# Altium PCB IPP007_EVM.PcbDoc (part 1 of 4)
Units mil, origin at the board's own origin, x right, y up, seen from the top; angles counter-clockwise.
Board outline 3500.95 x 3103 mil, 6 copper layers (Top Layer, Int1 (GND), Int2 (Sign), Int3 (Sign), Int4 (GND), Bottom Layer), stack 61.068 mil thick; 257 components, 132 nets, 1052 pads, 535 vias.
Unrouted connection lines stored in the file: 3.
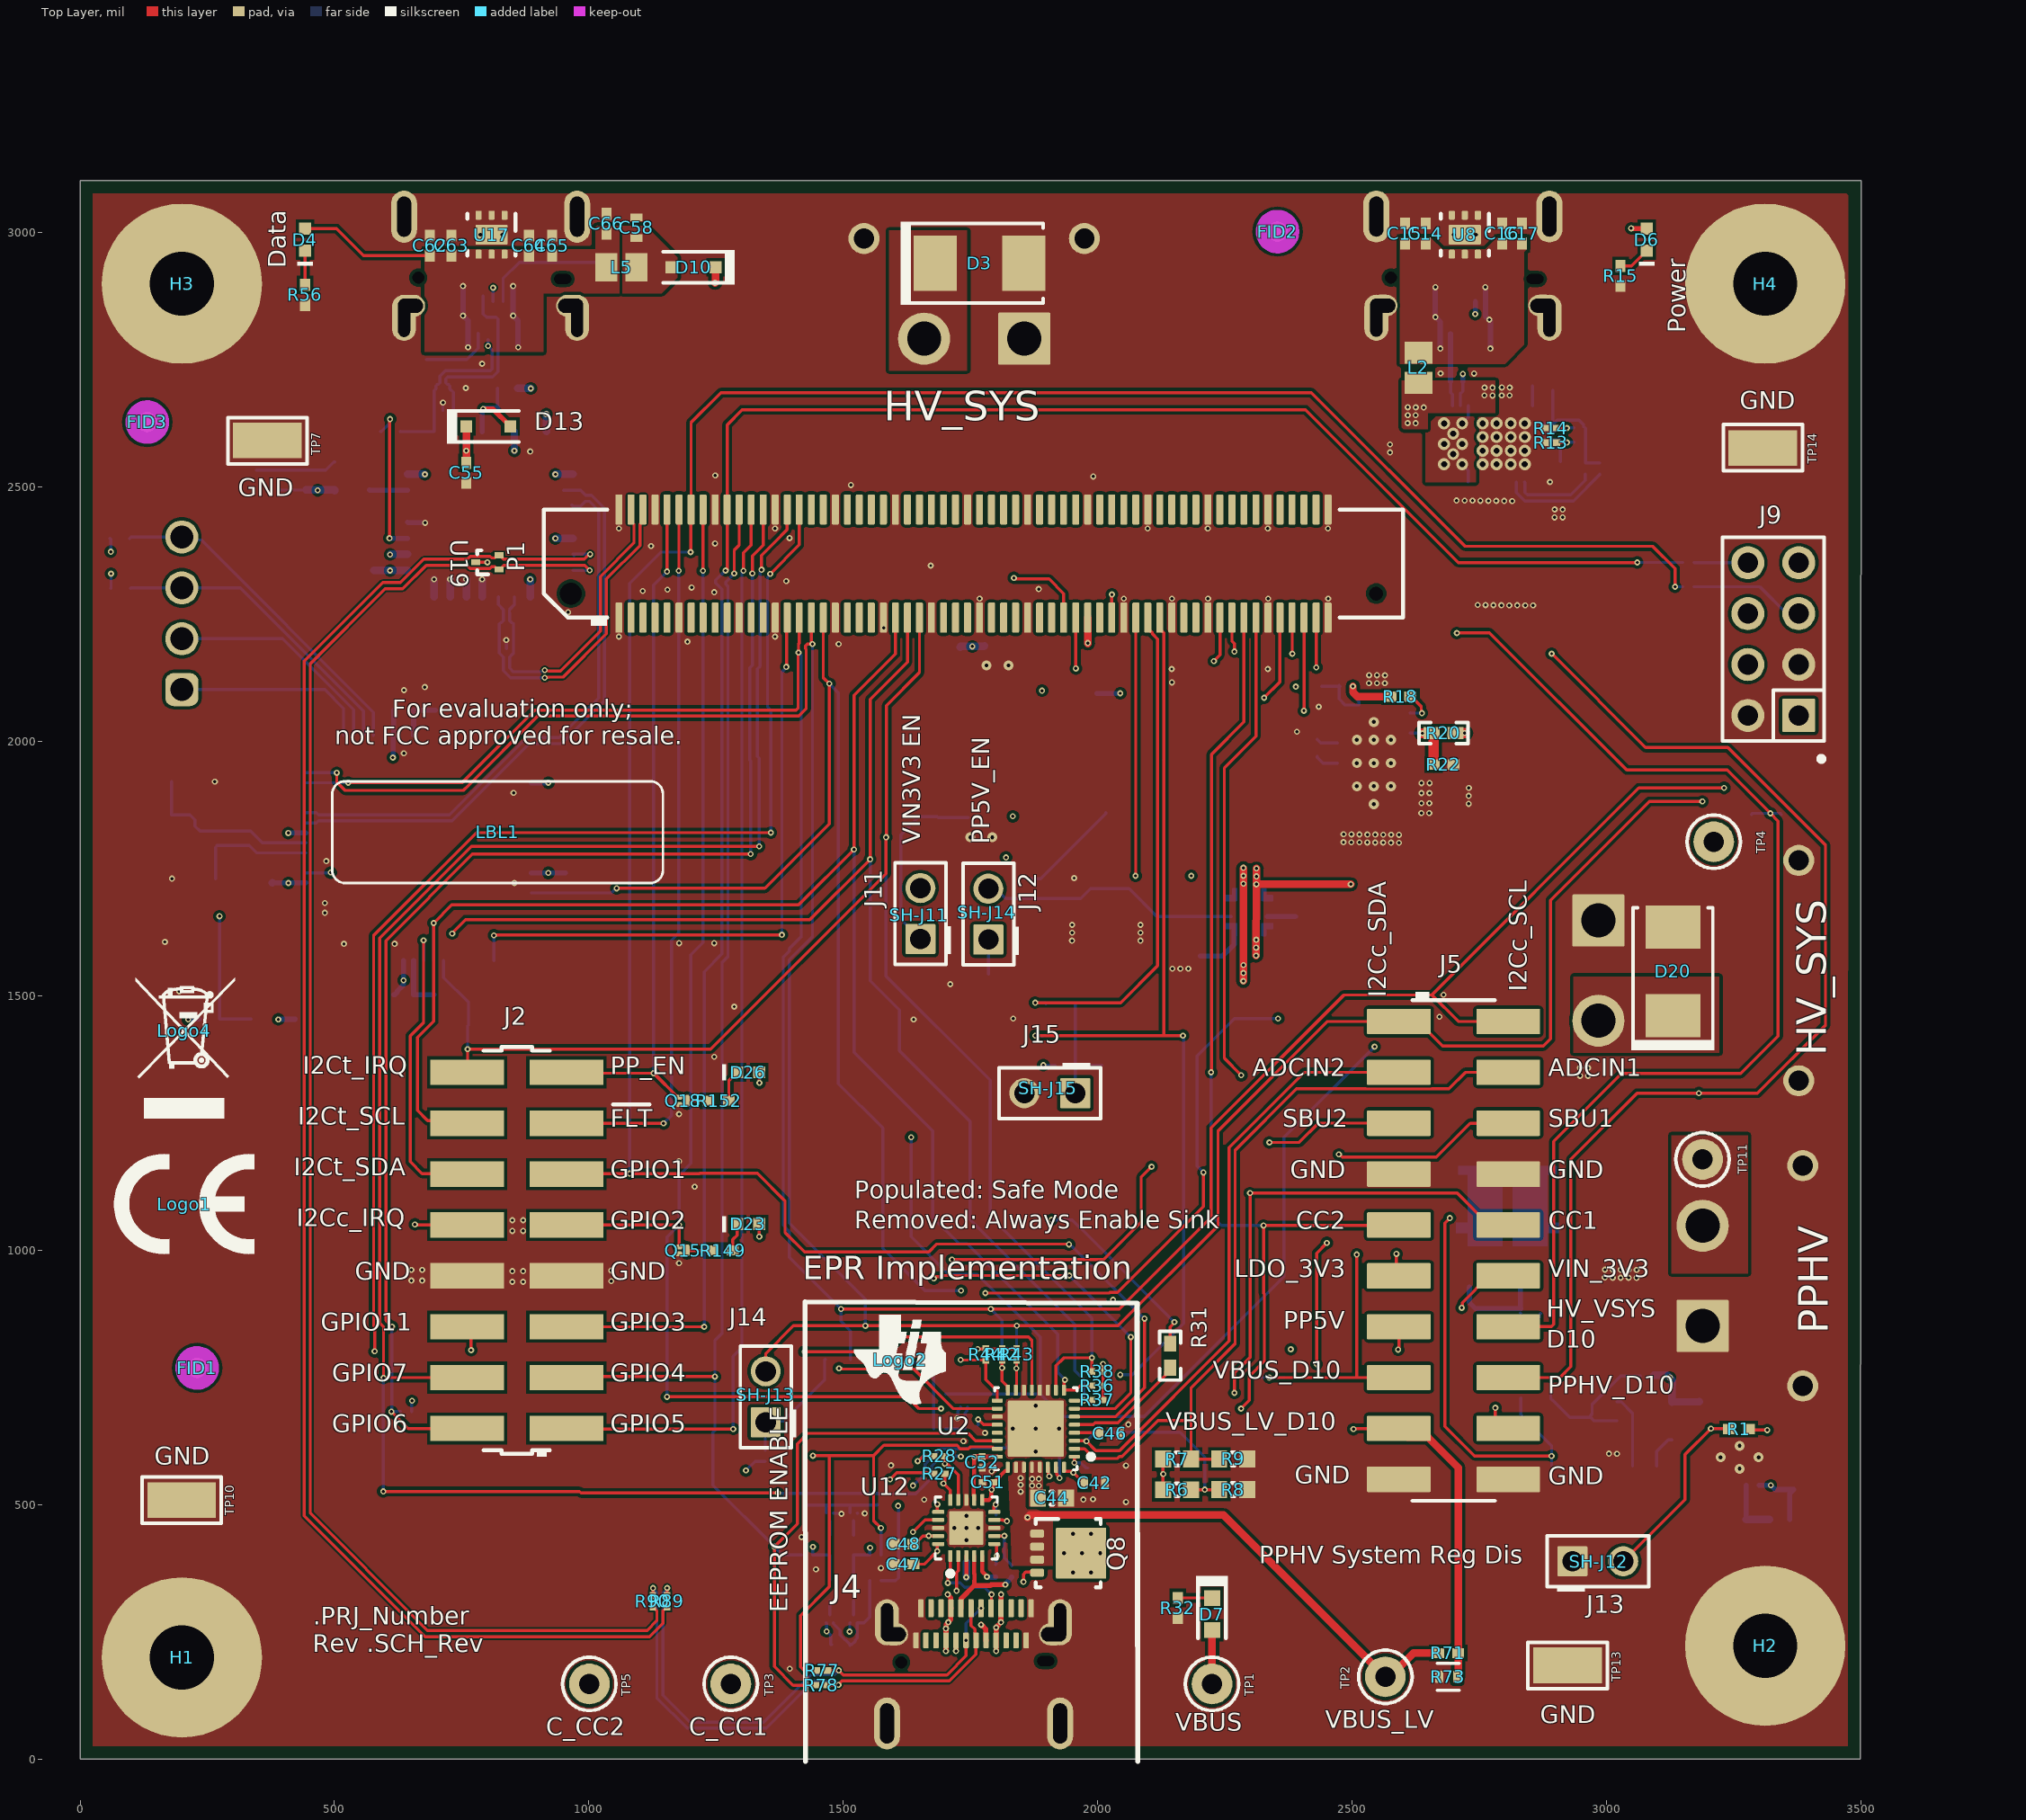
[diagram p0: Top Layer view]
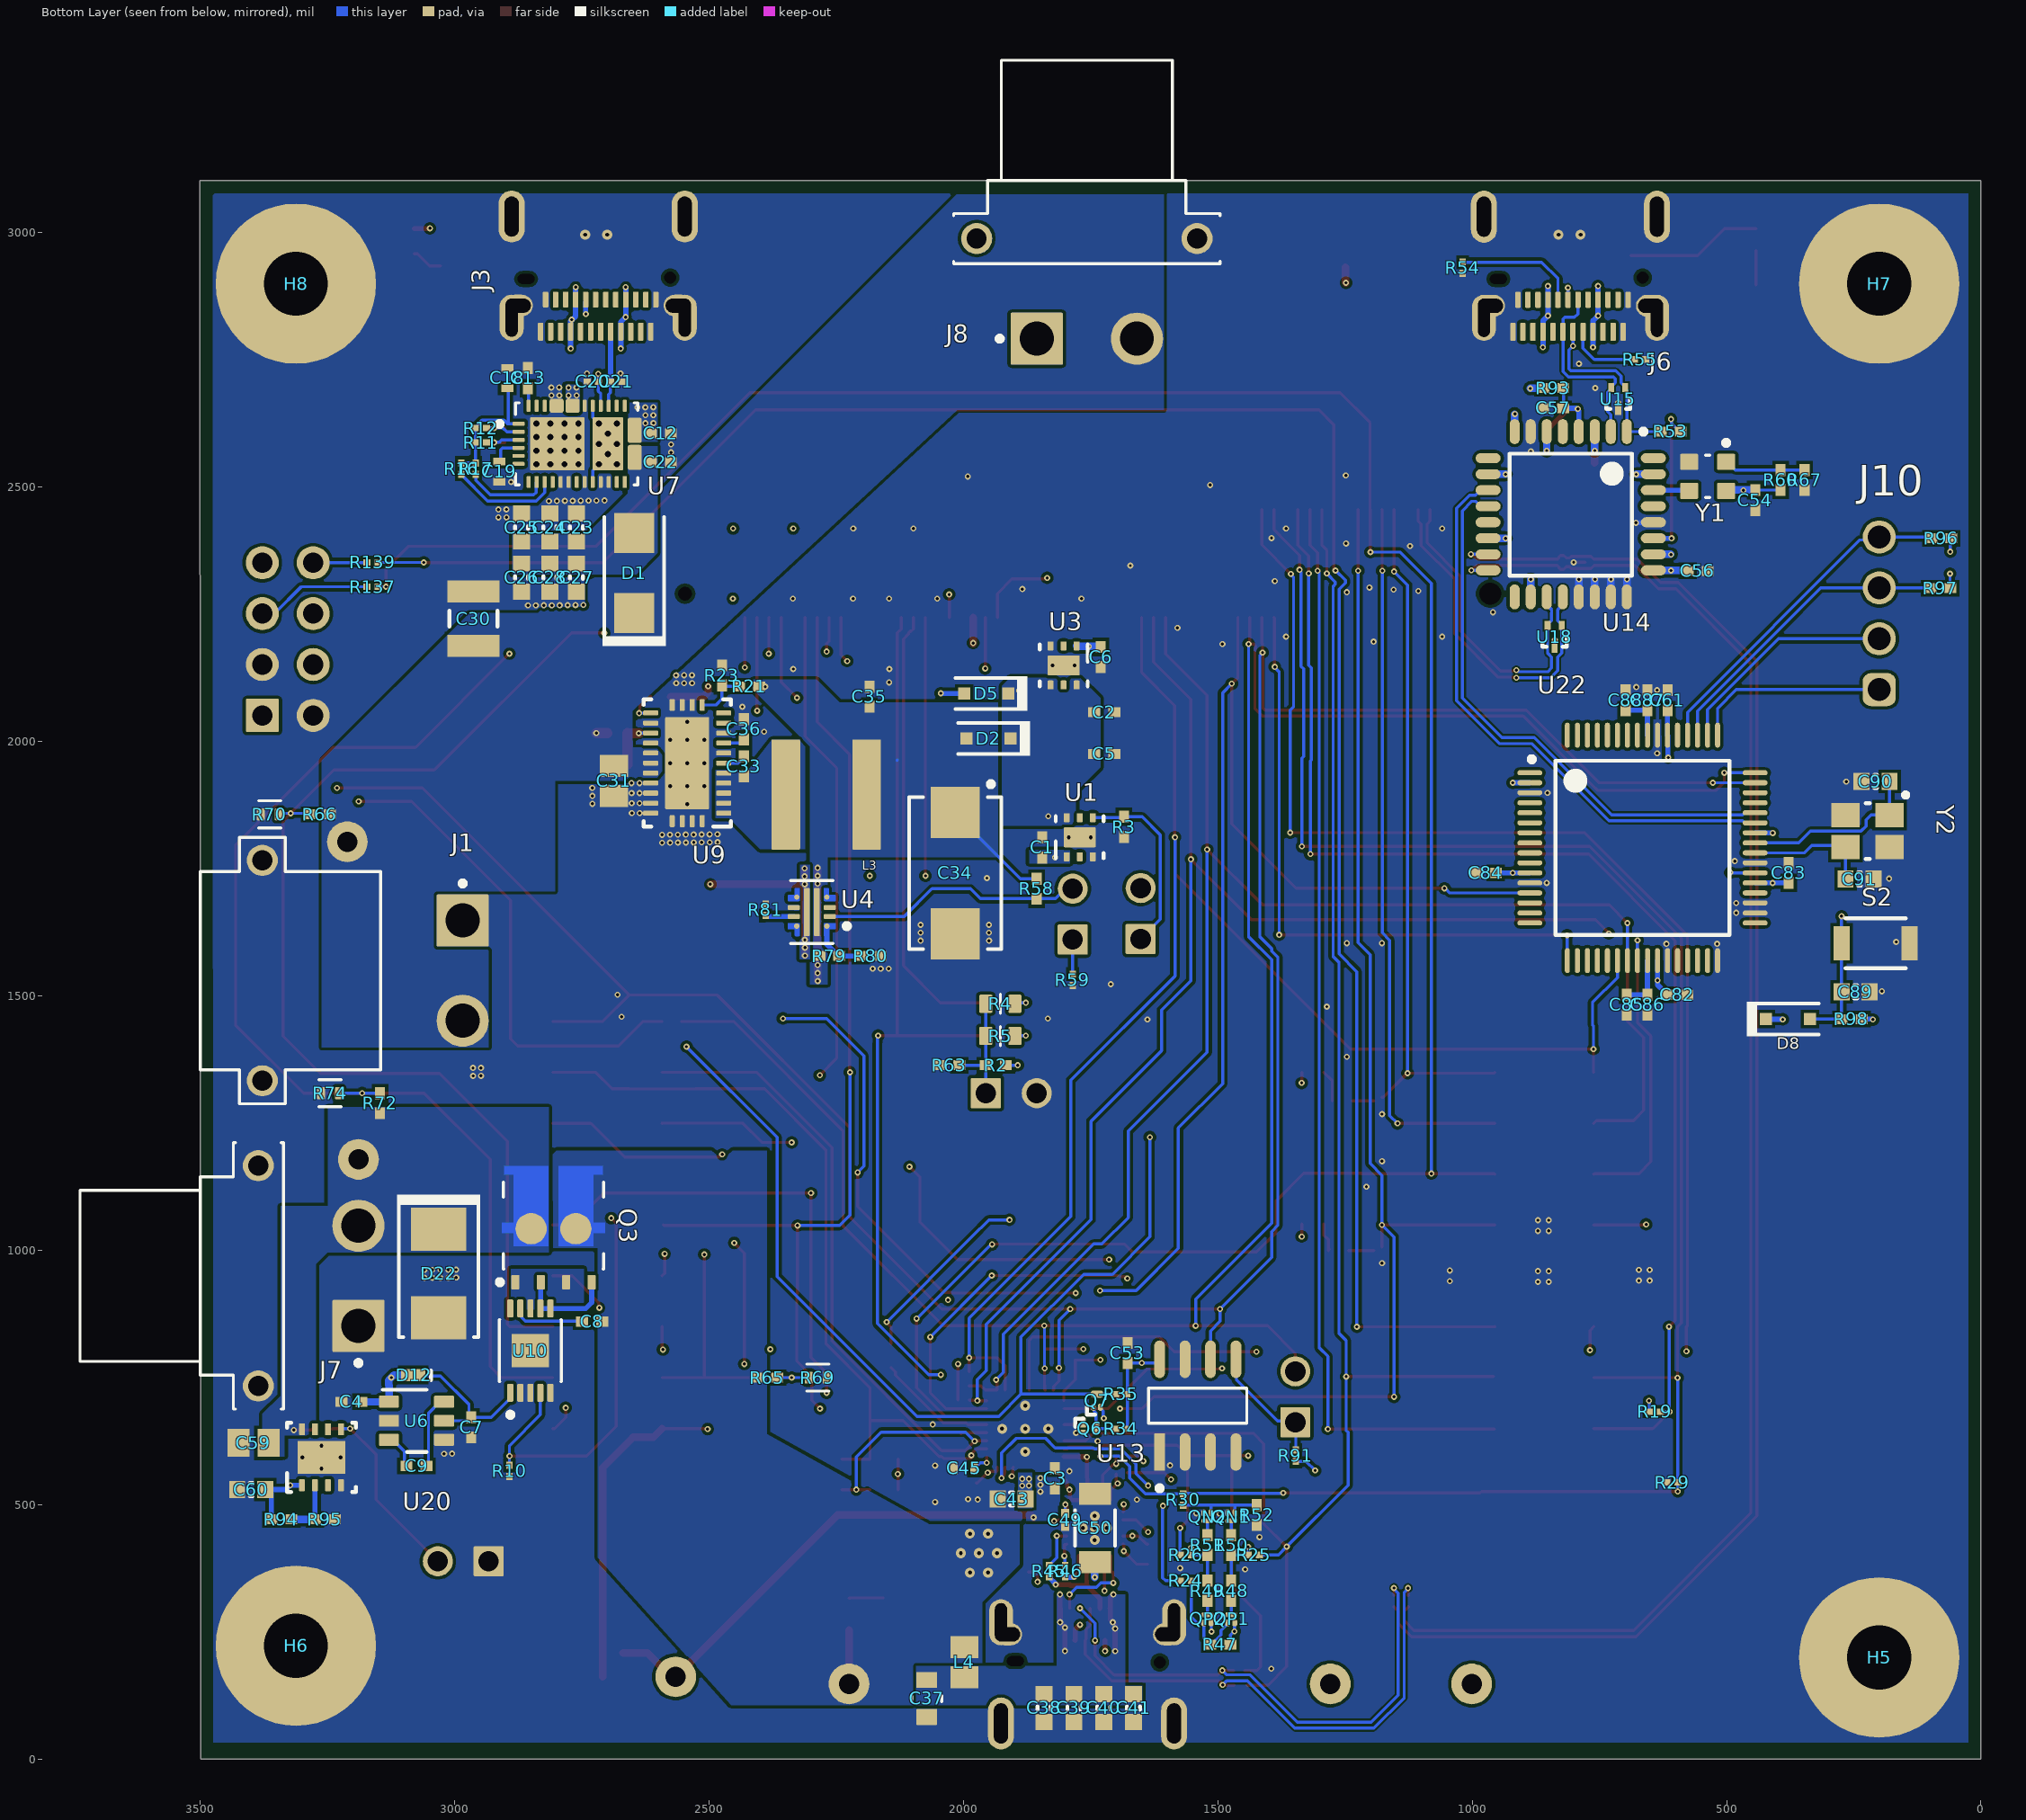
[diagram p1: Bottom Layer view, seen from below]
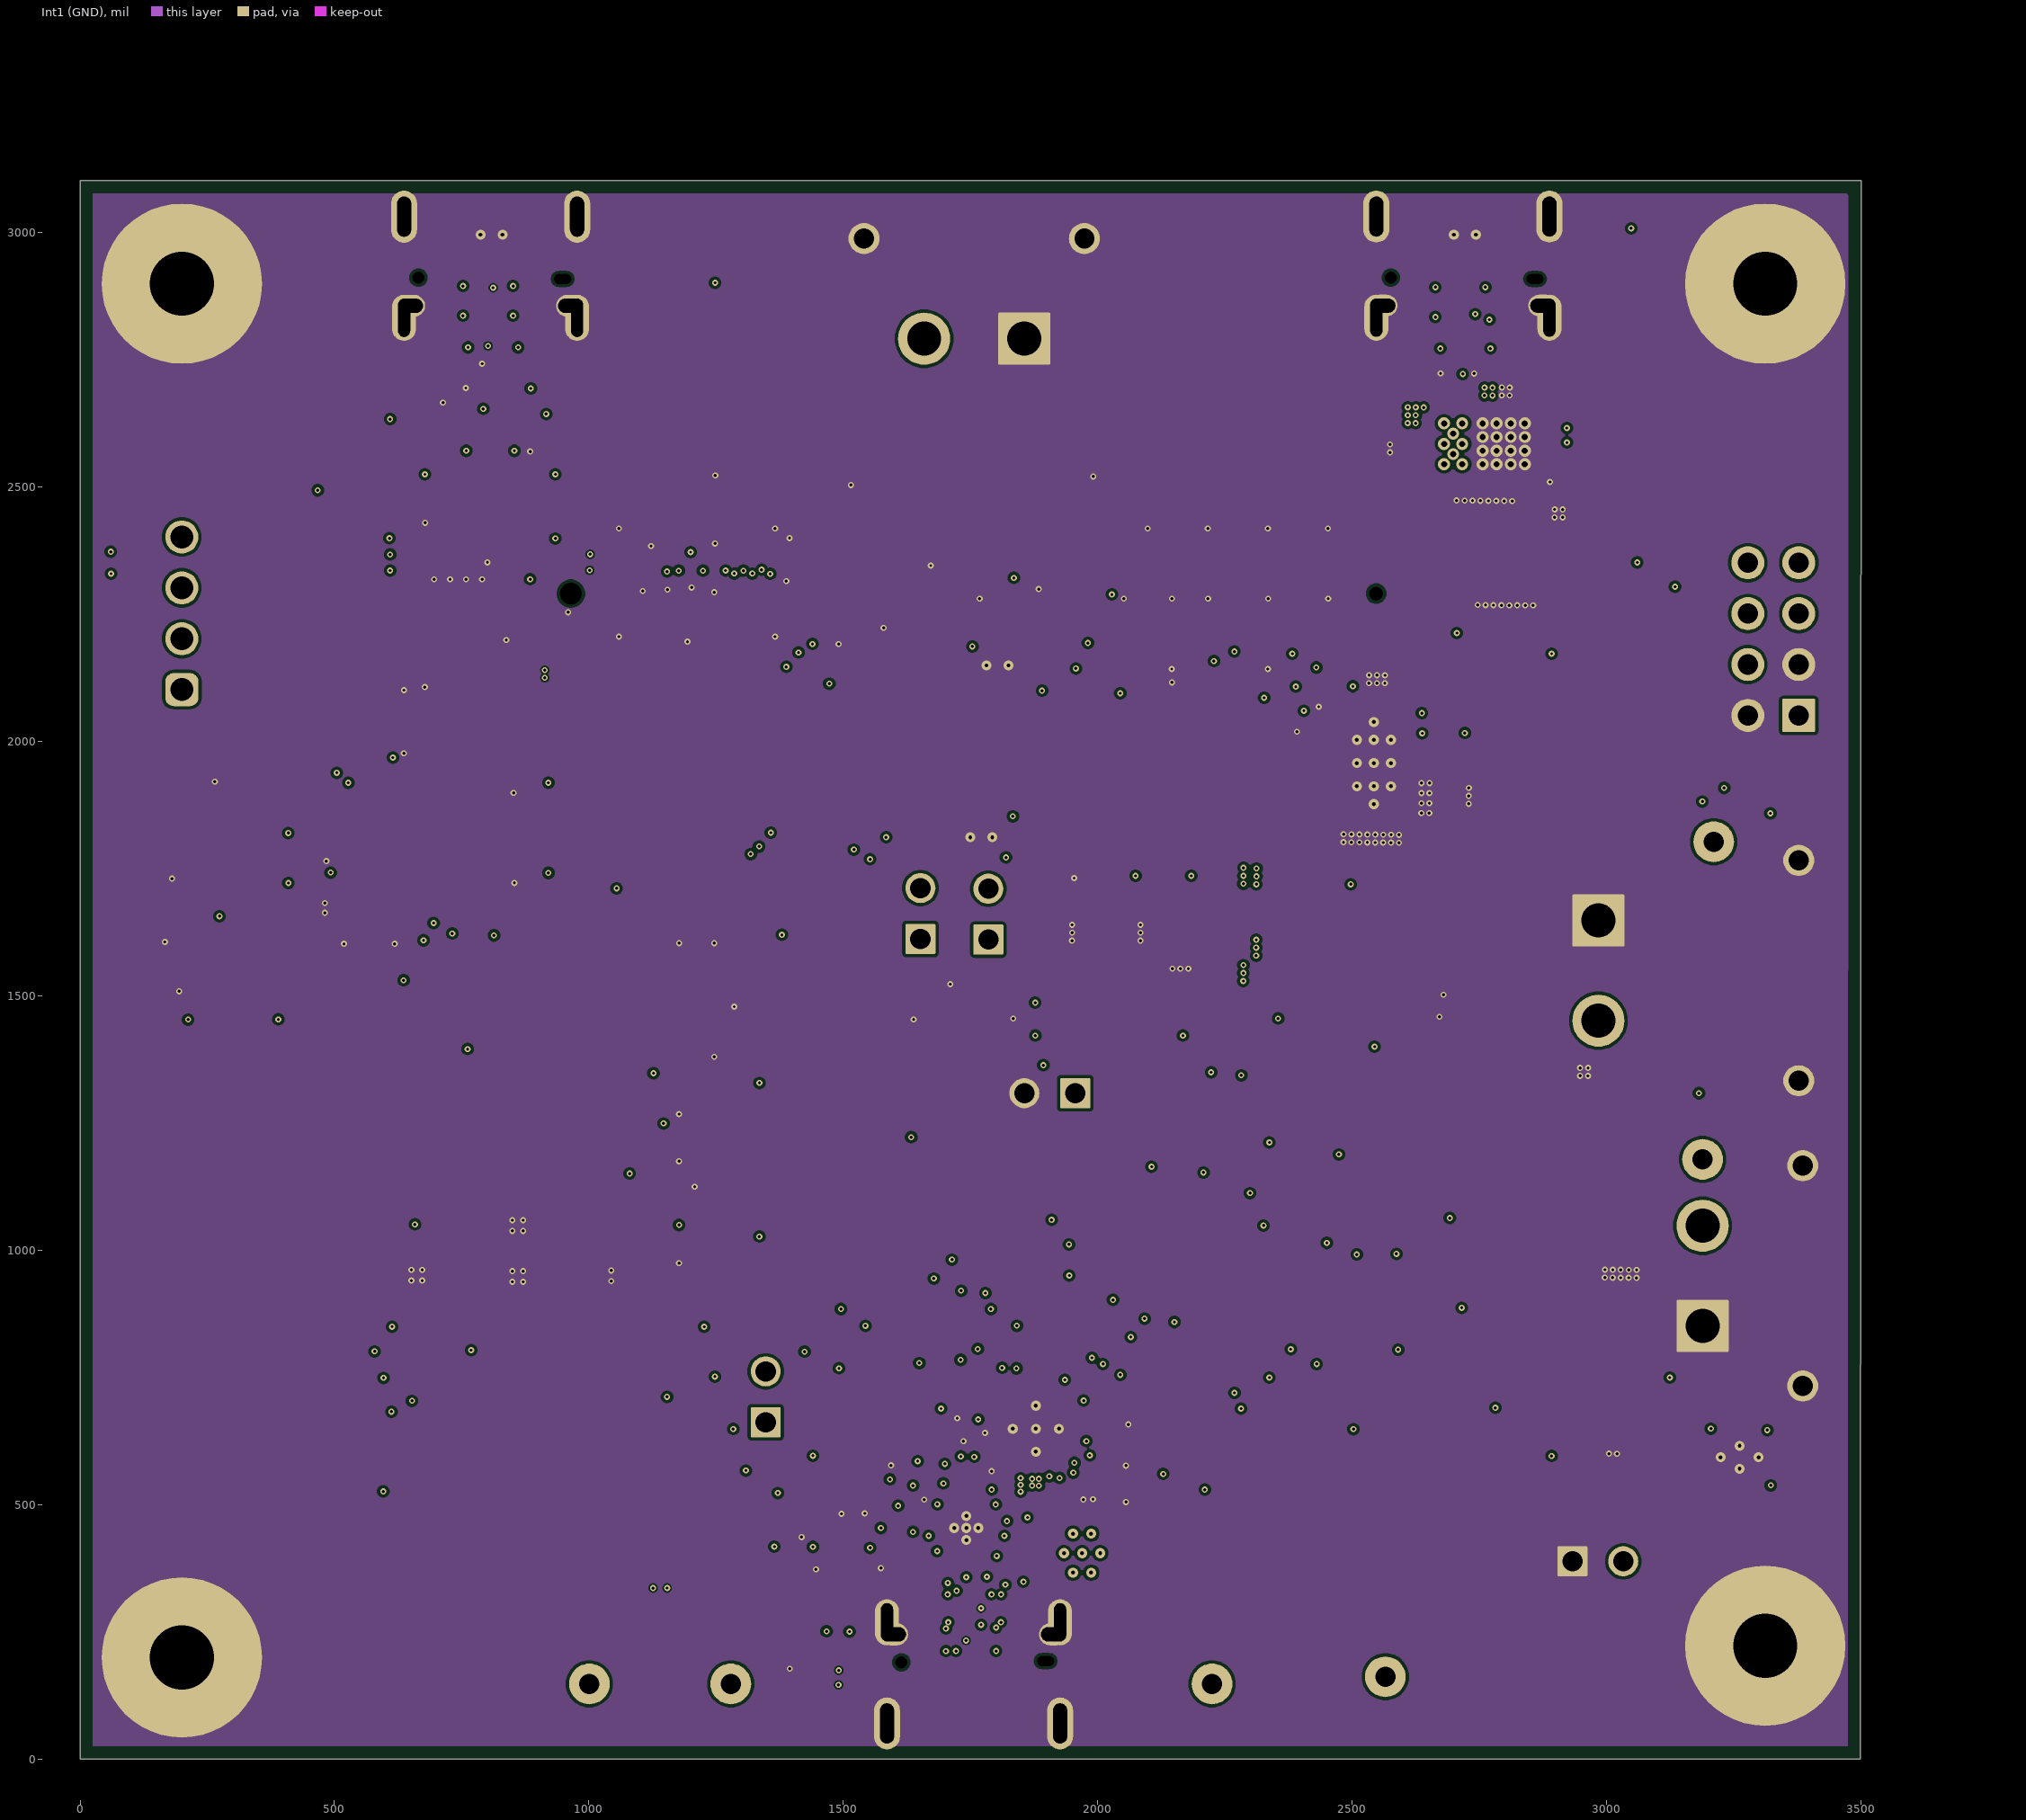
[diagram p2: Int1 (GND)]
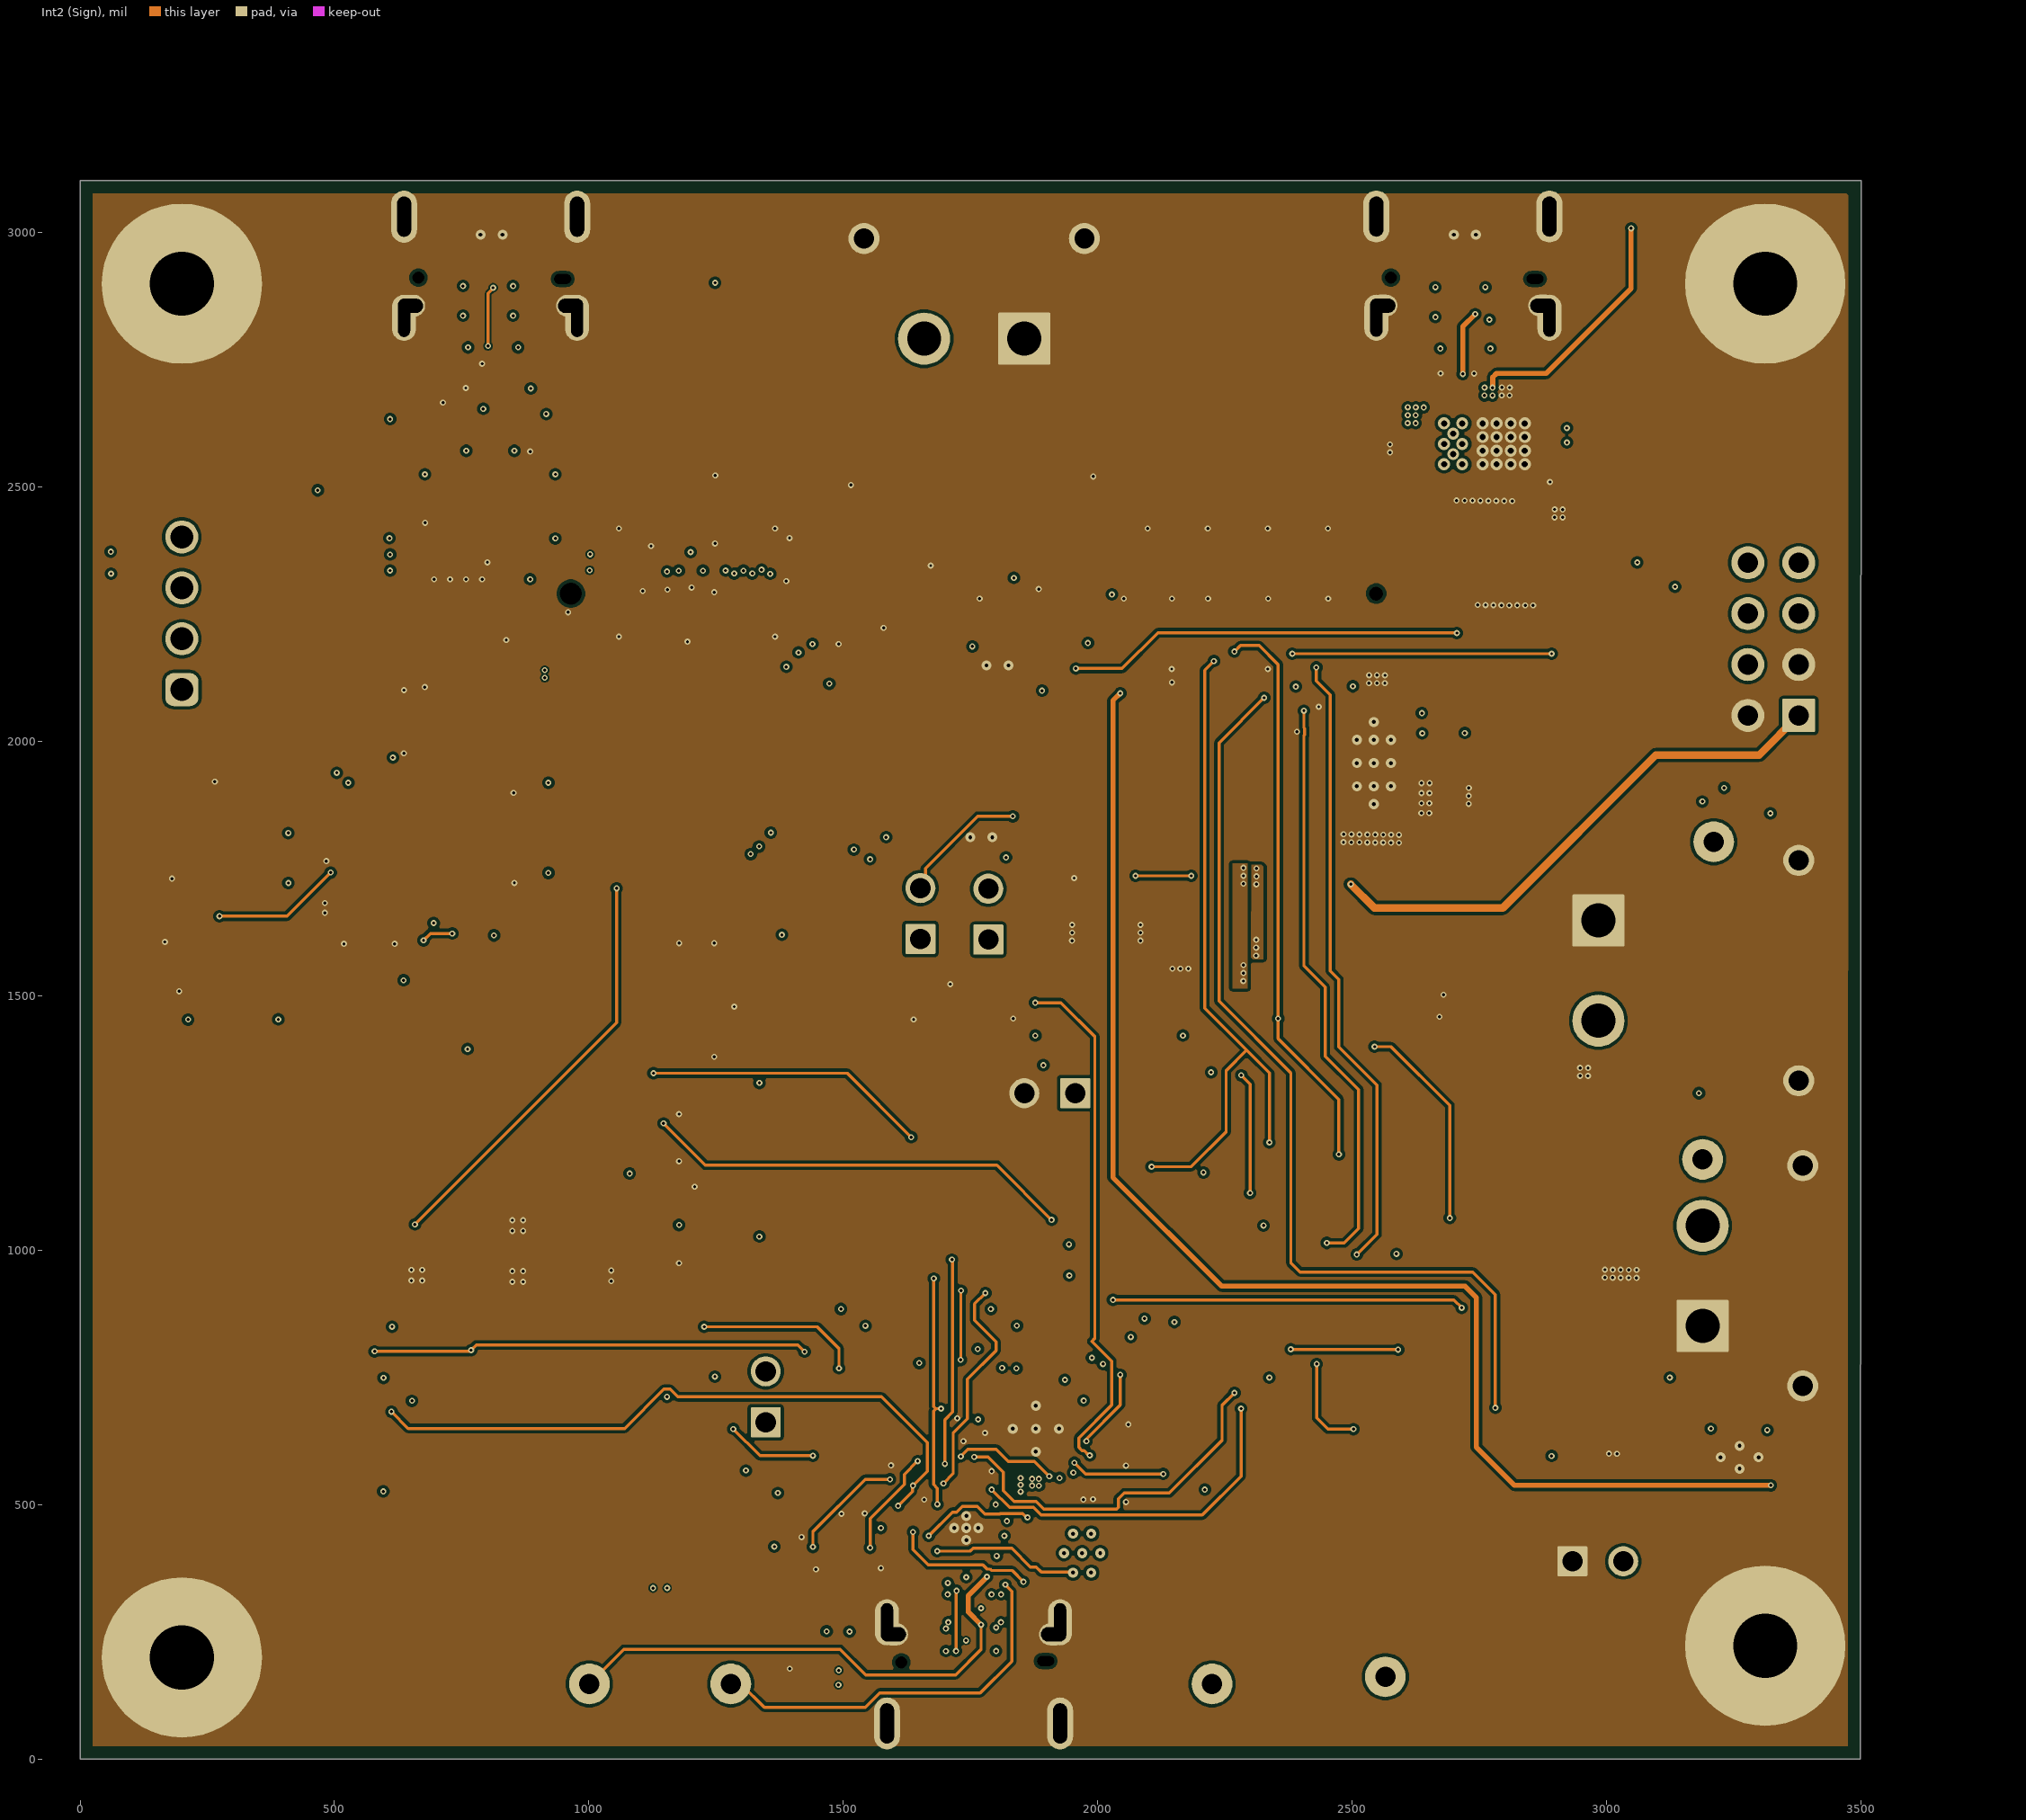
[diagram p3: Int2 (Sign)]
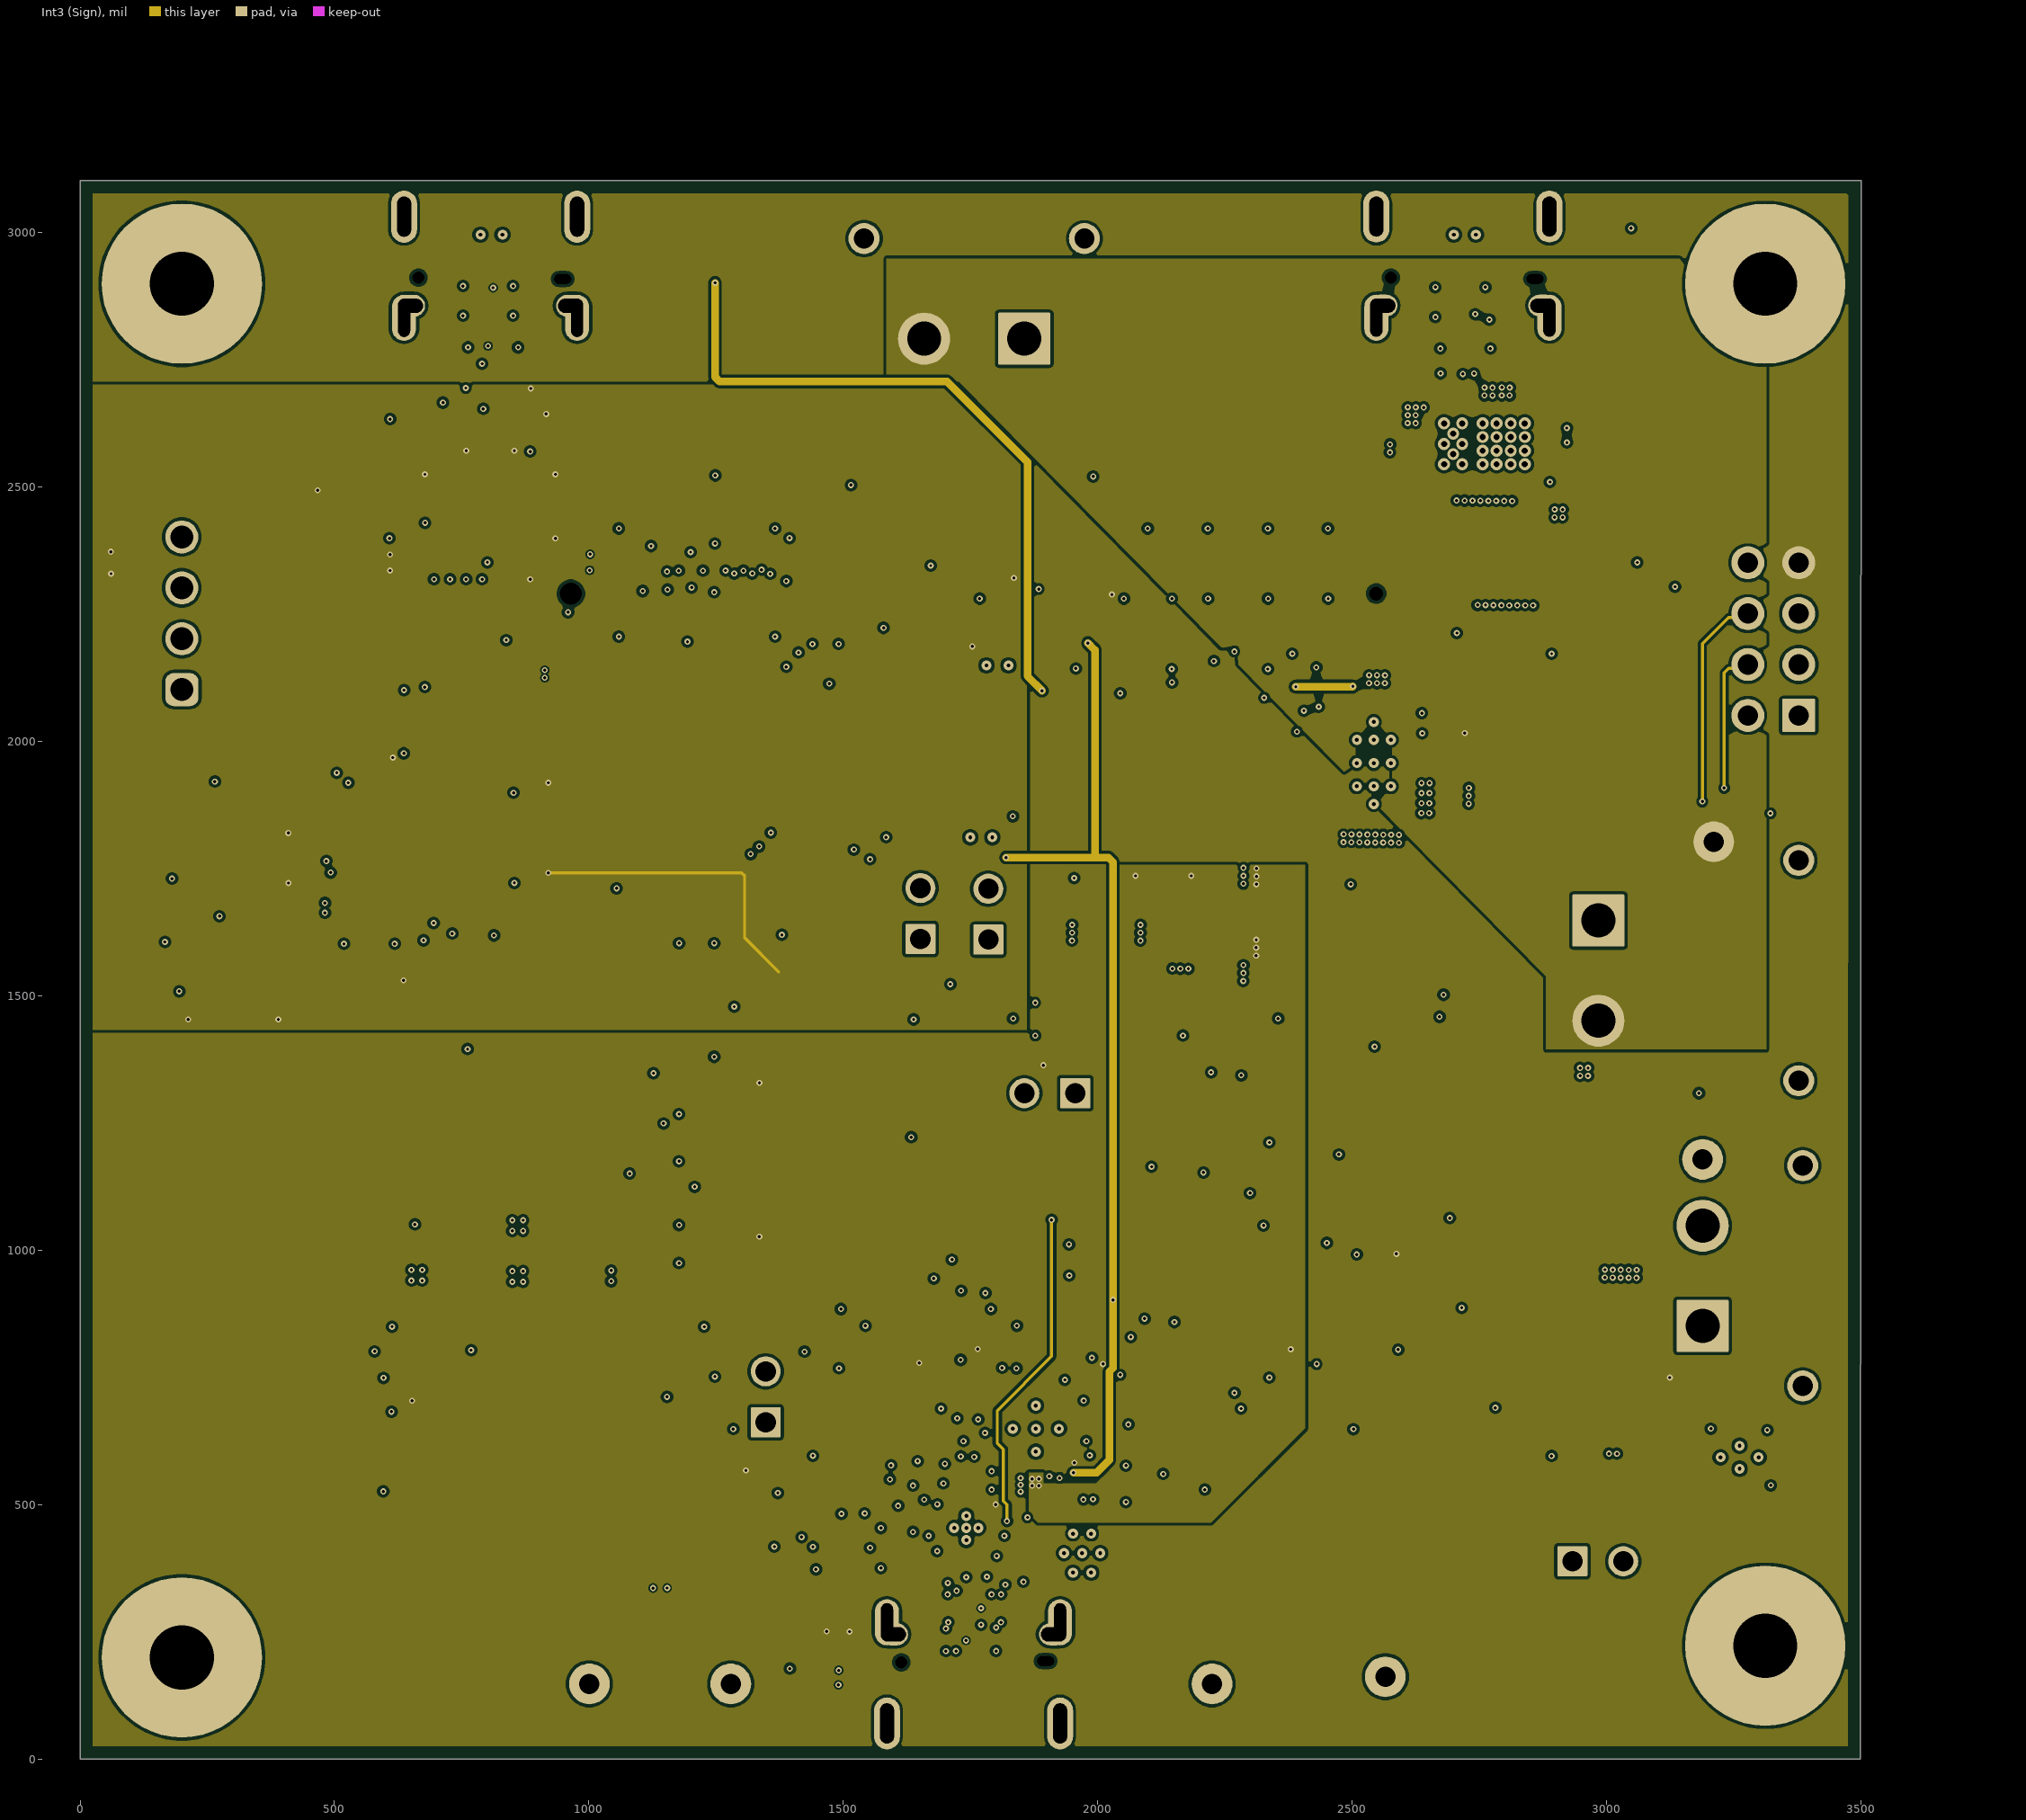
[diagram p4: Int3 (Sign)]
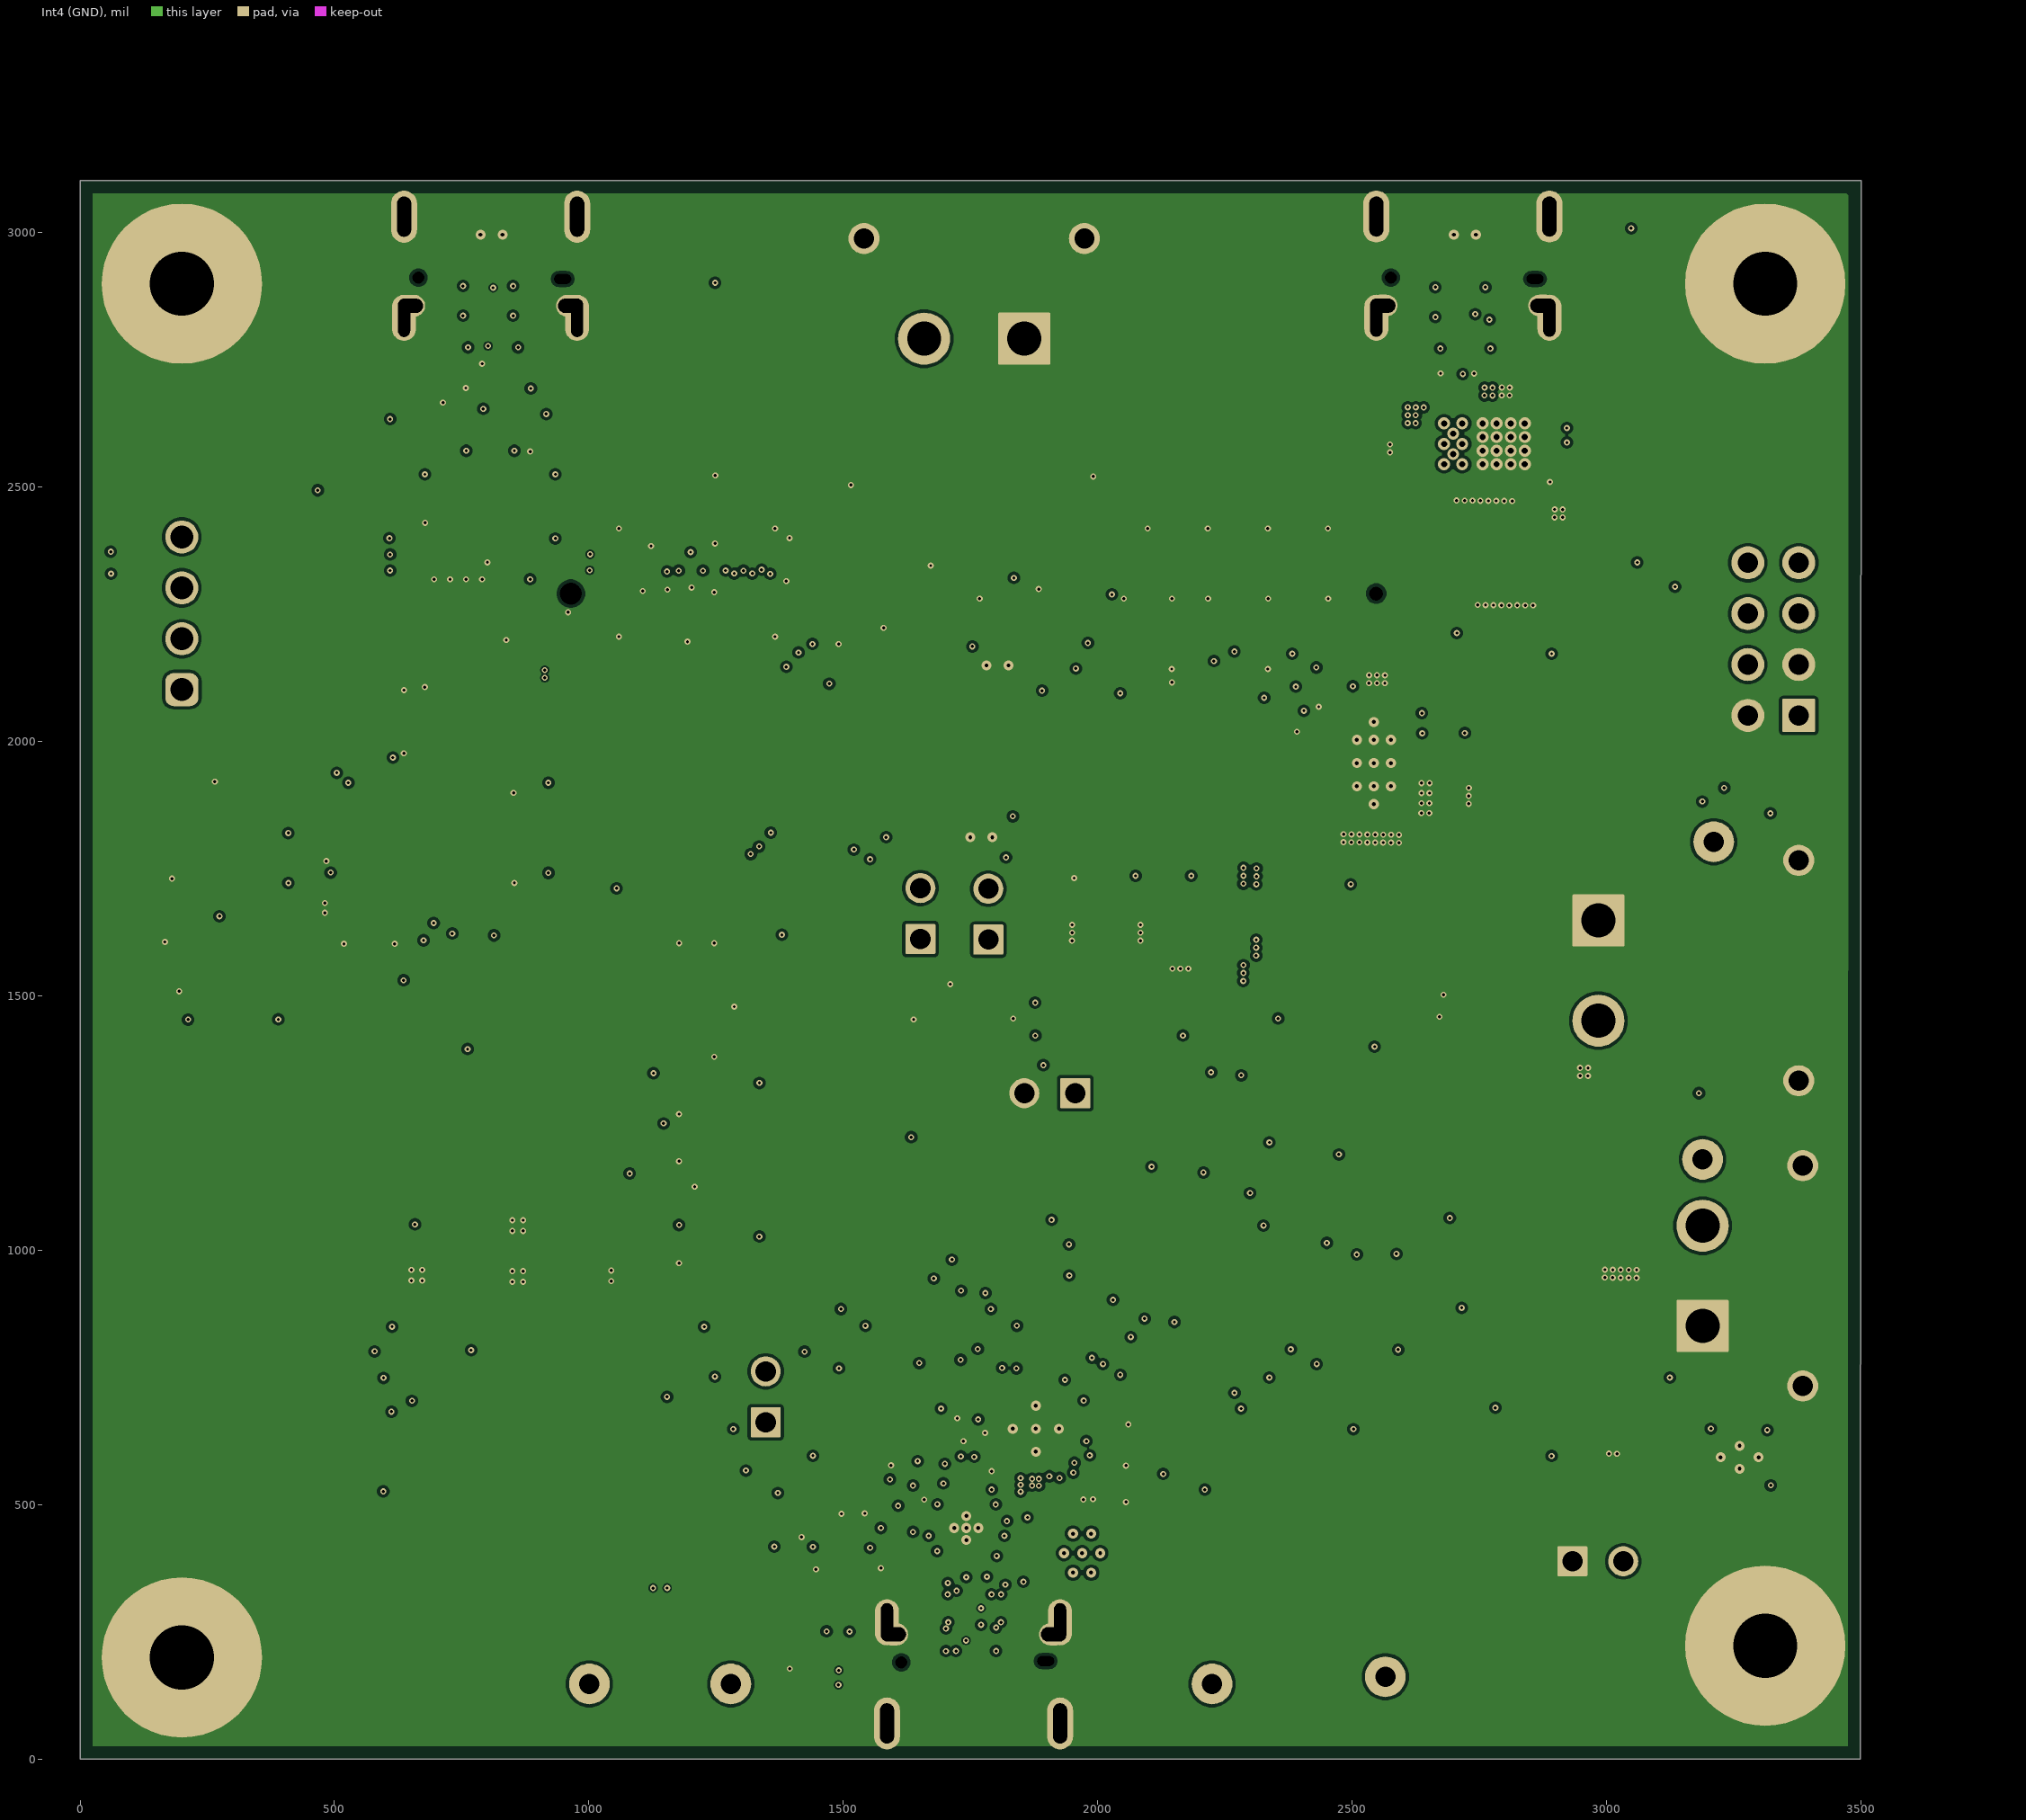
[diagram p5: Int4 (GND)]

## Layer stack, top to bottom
Top Solder: solder mask 1, SM-001, Dk 4
Top Layer: signal copper 1.378
Dielectric 1: prepreg 2.8, PP-006, Dk 4.1
Dielectric 2: prepreg 2.8, PP-006, Dk 4.1
Int1 (GND): signal copper 1.378
Dielectric 3: core 18, Core-035, Dk 4.7
Int2 (Sign): signal copper 1.378
Dielectric 4: prepreg 2.8, PP-006, Dk 4.1
Dielectric 5: prepreg 2.8, PP-006, Dk 4.1
Int3 (Sign): signal copper 1.378
Dielectric 6: core 18, Core-035, Dk 4.7
Int4 (GND): signal copper 1.378
Dielectric 7: prepreg 2.8, PP-006, Dk 4.1
Dielectric 8: prepreg 2.8, PP-006, Dk 4.1
Bottom Layer: signal copper 1.378
Bottom Solder: solder mask 1, SM-001, Dk 4

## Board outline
0,0 3499.35,0 3500.95,3103 0,3103

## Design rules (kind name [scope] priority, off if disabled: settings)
AcuteAngle [All] p1: minimum=4.50000000000000E+0001 checktracksonly=FALSE
AssemblyTestPointUsage [All] p1: valid=2
BoardOutlineClearance BoardOutlineClearance_MountingHoles [OnCopper and InComponentClass('Mounting Holes')] p1: gap=39.37 ignorepadtopadclearanceinfootprint=FALSE
BoardOutlineClearance BoardOutlineClearance_Poly [OnCopper and IsPoly] p2: gap=25 ignorepadtopadclearanceinfootprint=FALSE
BoardOutlineClearance [OnCopper and Not InComponentClass('Logo') and not InComponentClass('FiducialMark') and not InRegion(1000,500,4000,800) and not InPoly] p3: gap=40 ignorepadtopadclearanceinfootprint=FALSE
Clearance Clearance_2 [(InDifferentialPairClass('All Differential Pairs'))] p1: gap=3 ignorepadtopadclearanceinfootprint=TRUE
Clearance Clearance_1 [InNamedPolygon('Bottom Layer-PP5V')] p2: gap=6 ignorepadtopadclearanceinfootprint=FALSE except(0: Arc-Hole Track-Hole SMDPad-Hole THPad-Hole Via-Hole Fill-Hole Poly-Hole Region-Hole Text-Hole)
Clearance Clearance_Keepouts [((IsTrack Or IsArc) And Not InPoly) And IsFree and IsKeepOut vs ((IsTrack Or IsArc) And Not InPoly) And IsFree and IsKeepOut] p3: gap=0 ignorepadtopadclearanceinfootprint=FALSE
Clearance Clearance_Poly [InPolygon] p4: gap=6 ignorepadtopadclearanceinfootprint=TRUE
Clearance Clearance_FiducialMark [IsKeepOut and InComponentClass('FiducialMark') vs IsPad and InComponentClass('FiducialMark')] p5: gap=0 ignorepadtopadclearanceinfootprint=FALSE
Clearance [All] p6: gap=6 ignorepadtopadclearanceinfootprint=TRUE except(4.7: Arc-SMDPad Track-SMDPad SMDPad-SMDPad SMDPad-Fill SMDPad-Poly SMDPad-Region)
ComponentClearance ComponentClearance_MountingHoles_FiducialMarks [InComponentClass('Mounting Holes') vs InComponentClass('FiducialMark')] p1: gap=50 collisioncheckmode=3 verticalgap=10 showdistances=FALSE
ComponentClearance ComponentClearance_Shunt [InComponentClass('Header') vs InComponentClass('Shunt')] p2: gap=0 collisioncheckmode=3 verticalgap=0 showdistances=FALSE
ComponentClearance ComponentClearance_Logo [InComponentClass('Logo')] p3: gap=30 collisioncheckmode=3 verticalgap=10 showdistances=FALSE
ComponentClearance ComponentClearance_ScrewToNut [(HasFootprint('NY PMS 440 0025 PH')) vs (HasFootprint('Keystone_1902C'))] p4: gap=5 collisioncheckmode=3 verticalgap=10 showdistances=FALSE
ComponentClearance ComponentClearance_MountingHoles [InComponentClass('Mounting Holes')] p5: gap=100 collisioncheckmode=3 verticalgap=100000 showdistances=FALSE
ComponentClearance ComponentClearance_SmallPassives [HasFootprint('0201*') or HasFootprint('0402*') or HasFootprint('0508') or HasFootprint('0603*') or HasFootprint('0612') or HasFootprint('0805*') or HasFootprint('0815*') or HasFootprint('0830*') or HasFootprint('1206*') or HasFootprint('1210*') or HasFootprint('1808*') or HasFootprint('1812*') or HasFootprint('1825*') or HasFootprint('2010*') or HasFootprint('2220*') or HasFootprint('2225*') or HasFootprint('2512*') or HasFootprint('2728*') or HasFootprint('3518*') vs HasFootprint('0201*') or HasFootprint('0402*') or HasFootprint('0508') or HasFootprint('0603*') or HasFootprint('0612') or HasFootprint('0805*') or HasFootprint('0815*') or HasFootprint('0830*') or HasFootprint('1206*') or HasFootprint('1210*') or HasFootprint('1808*') or HasFootprint('1812*') or HasFootprint('1825*') or HasFootprint('2010*') or HasFootprint('2220*') or HasFootprint('2225*') or HasFootprint('2512*') or HasFootprint('2728*') or HasFootprint('3518*')] p6: gap=14.96 collisioncheckmode=3 verticalgap=10 showdistances=FALSE
ComponentClearance ComponentClearance_THtoSMT [IsThruComponent vs IsSMTComponent] p7: gap=30 collisioncheckmode=3 verticalgap=30 showdistances=FALSE
ComponentClearance ComponentClearance_THtoTH [IsThruComponent vs IsThruComponent] p8: gap=20 collisioncheckmode=3 verticalgap=30 showdistances=FALSE
ComponentClearance [All] p9: gap=20 collisioncheckmode=3 verticalgap=10 showdistances=FALSE
DiffPairsRouting [InDifferentialPairClass('All Differential Pairs')] p1: maxlimit=7.5 minlimit=5 mostfreqgap=6 toplayer_mingap=6 toplayer_minwidth=6 toplayer_maxwidth=7.5 toplayer_prefwidth=6 midlayer1_prefgap=5 midlayer1_minwidth=5 midlayer1_maxwidth=7.5 midlayer1_prefwidth=5 midlayer2_prefgap=5 midlayer2_minwidth=5 midlayer2_maxwidth=7.5 midlayer2_prefwidth=5 midlayer3_mingap=6 midlayer3_minwidth=6 midlayer3_maxwidth=7.5 midlayer3_prefwidth=6 midlayer5_mingap=6 midlayer5_minwidth=6 midlayer5_maxwidth=7.5 midlayer5_prefwidth=6 bottomlayer_mingap=6 bottomlayer_minwidth=6 bottomlayer_maxwidth=7.5 bottomlayer_prefwidth=6 maxuncoupledlength=1000
FabricationTestPointUsage TestPointUsage [All] p1: valid=2 allowmultiple=FALSE
FabricationTestpoint Testpoint [All] p1: side=3 testpointundercomponent=TRUE minsize=40 maxsize=100 preferedsize=60 minholesize=0 maxholesize=40 preferedholesize=32 testpointgrid=1 allowsidetop=TRUE allowsidebottom=TRUE usegrid=TRUE gridtolerance=0.01
FanoutControl Fanout_LCC [IsLCC] p1: bgadir=Out bgaviamode=Centered fanoutstyle=Auto fanoutdirection=Alternating viagrid=1 // Fanout_LCC (Default Rule)
FanoutControl Fanout_BGA [IsBGA] p2: bgadir=Out bgaviamode=Centered fanoutstyle=Auto fanoutdirection=Alternating viagrid=1 // Fanout_BGA (Default Rule)
FanoutControl Fanout_Default [All] p4: bgadir=Out bgaviamode=Centered fanoutstyle=Auto fanoutdirection=Alternating viagrid=1 // Fanout_Default (Default Rule)
FanoutControl Fanout_Small [(CompPinCount < 5)] p5: bgadir=Out bgaviamode=Centered fanoutstyle=Auto fanoutdirection=OutThenIn viagrid=1 // Fanout_Small (Default Rule)
HoleSize [All] p1: absolutevalues=TRUE maxlimit=251 minlimit=6 maxpercent=80.000 minpercent=20.000
HoleToHoleClearance [All] p1: gap=6 allowstackedmicrovias=TRUE
MinimumAnnularRing MinimumAnnularRing_ThermalPadVias [IsVia and InAnyComponent] p1: minimumring=5.91
MinimumAnnularRing [All] p2: minimumring=3
MinimumSolderMaskSliver MinimumSolderMaskSliver_Logo [InComponentClass('Logo') vs InComponentClass('Logo')] p1: minsoldermaskwidth=0.7
MinimumSolderMaskSliver [All] p2: minsoldermaskwidth=3.74
PlaneClearance [All] p1: clearance=7
PlaneConnect [All] p1: planeconnectstyle=Direct reliefexpansion=10 reliefentries=4 reliefconductorwidth=10 reliefairgap=10
PolygonConnect [All] p1: connectstyle=Direct reliefconductorwidth=10 reliefentries=4 polygonreliefangle="90 Angle" airgapwidth=10
RoutingLayers [All] p1: top layer_v5=TRUE mid layer 1_v5=FALSE mid layer 2_v5=TRUE mid layer 3_v5=TRUE mid layer 5_v5=TRUE bottom layer_v5=TRUE
RoutingVias [All] p1: holewidth=6 width=12 viastyle="Through Hole" minholewidth=6 minwidth=12 maxholewidth=40 maxwidth=65
RoutingVias ThermalPadVias [IsVia and InAnyComponent] p2: holewidth=7.87 width=19.68 viastyle="Through Hole" minholewidth=7.87 minwidth=15.75 maxholewidth=11.81 maxwidth=23.62
SilkToBoardRegionClearance [Not ((IsComment or IsDesignator) And (Hide <> 'False')) and not InRegion(1000,500,4000,800)] p1:
SilkToSilkClearance SilkToSilkClearance_Pb-FreeLogo [(HasFootprint('Pb-Free_Overlay_Medium') OR HasFootprint('Pb-Free_Overlay_Small')) vs (HasFootprint('Pb-Free_Overlay_Medium') OR HasFootprint('Pb-Free_Overlay_Small'))] p1: silktosilkclearance=0
SilkToSilkClearance [All] p2: silktosilkclearance=3.94
SilkToSolderMaskClearance SilkToComponentPadClearance [(IsPad or IsFill or IsRegion) and InAnycomponent] p1: minsilkscreentomaskgap=5 clearancetoexposedcopper=TRUE
SilkToSolderMaskClearance "Silk to Solder Mask Opening" [All] p2: minsilkscreentomaskgap=3.94 clearancetoexposedcopper=FALSE
SolderMaskExpansion "VIA Fill" [IsVia] p1: expansion=4 istentingtop=TRUE
SolderMaskExpansion [All] p2: expansion=1.97 istentingtop=FALSE
SupplyNets "Schematic Supply Nets" [InNet('LDO_3V3')] p1: voltage=0.000
UnRoutedNet [All] p1: checkbadconnections=TRUE
Width [All] p1: maxlimit=100 minlimit=6 preferedwidth=6 minimp=50.000000 maximp=50.000000 favimp=50.000000
11 further rules are at their usual default settings.

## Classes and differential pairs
component class Shunt: SH-J11 SH-J12 SH-J13 SH-J14 SH-J15
component class U_IPP007_TC_POWER: C12 C13 C14 C15 C16 C17 C18 C19 C20 C21 C22 C23 C24 C25 C26 C27 C28 D6 J3 L2 R11 R12 R13 R14 R15 R16 R17 U7 U8
component class U_IPP007_SystemPower: D1
component class U_IPP007_BIDI_PP: C4 C7 C8 C9 D12 Q3 R10 U6 U10
component class "Mounting Holes": H1 H2 H3 H4
component class U_IPP007_RP_HOST: C61 C82 C83 C84 C85 C86 C87 C88 C89 C90 C91 D8 D18 J10 R96 R97 R98 S2 U22 Y2
component class U_MD: QN1 QN2 QP1 QP2 R24 R25 R26 R27 R28 R30 R47 R48 R49 R50 R51 R52
component class U_IPP007_CONNECTORS: C70 C72 C74 C75 D3 D14 D15 D17 D20 D22 D23 D26 J1 J2 J5 J7 J8 J9 J15 L1 m P1 Q2 Q10 Q12 Q15 Q18 R2 R4 R5 R19 R29 R63 R65 R66 R69 R70 R71 R72 R73 R74 R92 R137 R139 R149 R152 TP1 TP2 TP4 TP6 TP7 TP8 TP9 TP10 TP11 TP13 TP14
component class Header: J2 J5 J9 J10 J11 J12 J13 J14 J15 J57
component class U_IPP007_HUB: C54 C55 C56 C57 C58 C62 C63 C64 C65 C66 D4 D13 J6 L5 R53 R54 R55 R56 R60 R67 R93 U14 U15 U17 U18 U19 Y1
component class U_PP5V_SUPPLY: C1 C2 C5 C6 C30 C31 C33 C34 C35 C36 C59 C60 C71 C72 D2 D5 D10 D16 J11 J12 J13 L3 Q11 R1 R3 R18 R20 R21 R22 R23 R58 R59 R79 R80 R81 R94 R95 U1 U3 U4 U9 U20
component class U_EVM_Hardware: !PCB FID1 FID2 FID3 H1 H2 H3 H4 H5 H6 H7 H8 LBL1 Logo1 Logo2 Logo3 Logo4 SH-J11 SH-J12 SH-J13 SH-J14 SH-J15 ZZ1 ZZ2 ZZ3 ZZ4 ZZ5
component class Logo: Logo2
component class Label: LBL1
component class FiducialMark: FID1 FID2 FID3
component class AssemblyNote: ZZ1 ZZ2 ZZ3 ZZ4 ZZ5
differential pair PD_D: +PD_D_P -PD_D_N
differential pair D3: +D3_P -D3_N
differential pair D2: +D2_P -D2_N
differential pair D1: +EXP_D_P -EXP_D_N
differential pair D: +D_P -D_N

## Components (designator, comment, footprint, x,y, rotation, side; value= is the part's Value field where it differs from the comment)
C1 "C1005X6S1C105K050BC" 0402L 1845.31,1791.96 r90 bottom value=1uF
C2 "C1005X6S1C105K050BC" 0402L 1723.21,2057.87 r180 bottom value=1uF
C3 "C1005X5R1H104K050BB" 0402L 1820.25,552.07 r90 bottom value=0.1uF
C4 "C1005X5R1A335K050BC" 0402L 3202.63,702.52 r0 bottom value=3.3uF
C5 "C1005X6S1C105K050BC" 0402L 1723.21,1975.97 r180 bottom value=1uF
C6 "C1005X6S1C105K050BC" 0402L 1729.95,2166.23 r270 bottom value=1uF
C7 "C1005X5R1A335K050BC" 0402L 2967.29,652.25 r90 bottom value=3.3uF
C8 "C1005X5R1E224M050BC" 0402L 2729.77,860 r0 bottom value=0.22uF
C9 "C1005X5R1A335K050BC" 0402L 3074.96,576.25 r180 bottom value=3.3uF
C12 "GRM155R6YA105KE11D" 0402L 2594.75,2605.83 r180 bottom value=1uF
C13 "GMK105BJ104KV-F" 0402L 2855.91,2714.58 r90 bottom value=0.1uF
C14 "C0402C103J5RACTU" 0402L 2644.71,2998.73 r90 top value=0.01uF
C15 "C0402C103J5RACTU" 0402L 2604.21,2998.73 r90 top value=0.01uF
C16 "C0402C103J5RACTU" 0402L 2795.05,2998.73 r90 top value=0.01uF
C17 "C0402C103J5RACTU" 0402L 2833.69,2998.73 r90 top value=0.01uF
C18 "CL05A106MP5NUNC" 0402_070 2896.53,2714.58 r270 bottom value=10uF
C19 "CL05A106MP5NUNC" 0402_070 2912.29,2530.8 r90 bottom value=10uF
C20 "CGA1A2X7R1H331K030BA" 0201_033L 2728.72,2707.61 r0 bottom value=330pF
C21 "CGA1A2X7R1H331K030BA" 0201_033L 2682.57,2707.61 r180 bottom value=330pF
C22 "GMK105BJ104KV-F" 0402L 2594.75,2549.24 r180 bottom value=0.1uF
C23 "GRM188R6YA106MA73D" 0603L 2760.52,2420.78 r90 bottom value=10uF
C24 "GRM188R6YA106MA73D" 0603L 2812.89,2420.78 r90 bottom value=10uF
C25 "GRM188R6YA106MA73D" 0603L 2868.18,2420.78 r90 bottom value=10uF
C26 "GRM188R6YA106MA73D" 0603L 2868.18,2322.38 r270 bottom value=10uF
C27 "GRM188R6YA106MA73D" 0603L 2760.52,2322.38 r270 bottom value=10uF
C28 "GRM188R6YA106MA73D" 0603L 2812.89,2322.38 r270 bottom value=10uF
C30 "C3225X7S2A475K200AE" 1210L 2962.88,2241.67 r90 bottom value=4.7uF
C31 "C2012X7S2A474K125AB" 0805L 2686.97,1922.95 r270 bottom value=0.47uF
C33 "GRM155R61A474KE15D" 0402L 2431.5,1951.55 r90 bottom value=0.47uF
C34 "TPSE227M016R0100" 7343-43 2015.89,1741.58 r270 bottom value=220uF
C35 "C1005X6S1C105K050BC" 0402L 2184.57,2088.33 r90 bottom value=1uF
C36 "C1005X6S1C225K050BC" 0402_065L 2431.5,2024.32 r90 bottom value=2.2uF
C37 "C2012X5R2A475K125AC" FP-C2012X5R2A475K125AC_0805-MFG 2072.16,119.42 r90 bottom value=4.7µF
C38 "C0603X103K1RACTU" 0603L 1841.53,100.5 r270 bottom value=0.01uF
C39 "C0603X103K1RACTU" 0603L 1782.84,100.5 r270 bottom value=0.01uF
C40 "C0603X103K1RACTU" 0603L 1724.15,100.5 r270 bottom value=0.01uF
C41 "C0603X103K1RACTU" 0603L 1665.46,100.5 r270 bottom value=0.01uF
C42 "CL05A106MP5NUNC" 0402_070 1994.11,542.77 r0 top value=10uF
C43 "GRM188R61E106MA73D" 0603L 1905.18,511.29 r0 bottom value=10uF
C44 "GRM188R61E106MA73D" 0603L 1910.18,513.48 r0 top value=10uF
C45 "CL05A106MP5NUNC" 0402_070 1998.79,572.38 r180 bottom value=10uF
C46 "CL05A106MP5NUNC" 0402_070 2024.11,639.9 r180 top value=10uF
C47 "GRM155R62A104KE14D" 0402L 1618.49,383.24 r180 top value=0.1uF
C48 "C1005X5R1H104K050BB" 0402L 1618.49,422.69 r180 top value=0.1uF
C49 "GRM033R60J105MEA2D" 0201_033 1800.18,470.33 r270 bottom value=1uF
C50 "C3216X7R2A474K160AA" 1206_180 1741.33,454.42 r90 bottom value=0.47uF
C51 "CGA1A2X7R1H221K030BA" 0201_033L 1784.96,544.25 r180 top value=220pF
C52 "CGA1A2X7R1H221K030BA" 0201_033L 1773.15,583.45 r270 top value=220pF
C53 "CGA2B3X7R1H104K050BB" 0402L 1677.33,798.34 r90 bottom value=0.1uF
C54 "GRM155R60J104KA01D" 0402L 443.86,2474.77 r270 bottom value=0.1uF
C55 "GRM155R60J104KA01D" 0402L 759.11,2528.33 r270 top value=0.1uF
C56 "GRM155R60J104KA01D" 0402L 557.02,2335.52 r180 bottom value=0.1uF
C57 "GRM155R60J104KA01D" 0402L 841.16,2655.28 r0 bottom value=0.1uF
C58 "0402ZD106MAT2A" 0402_080S 1093.61,3010.18 r90 top value=10uF
C59 "C2012X7S2A105K125AE" 0805L 3395.39,621.76 r0 bottom value=1uF
C60 "GRM188Z71C225KE43" 0603L 3399.68,529.84 r0 bottom value=2.2uF
C61 "CGA2B3X7R1H104K050BB" 0402L 616.18,2081.49 r90 bottom value=0.1uF
C62 "C0402C103J5RACTU" 0402L 687.6,2974.98 r90 top value=0.01uF
C63 "C0402C103J5RACTU" 0402L 730.19,2974.98 r90 top value=0.01uF
C64 "C0402C103J5RACTU" 0402L 882.22,2974.98 r90 top value=0.01uF
C65 "C0402C103J5RACTU" 0402L 927.73,2974.98 r90 top value=0.01uF
C66 "CC0402MRX5R6BB105" 0402L 1034.56,3018.12 r90 top value=1uF
C82 "CGA2B3X7R1H104K050BB" 0402L 596.66,1502.47 r180 bottom value=0.1uF
C83 "CGA2B3X7R1H104K050BB" 0402L 378,1742 r90 bottom value=0.1uF
C84 "CGA2B3X7R1H104K050BB" 0402L 973.79,1741.97 r0 bottom value=0.1uF
C85 "C1005X5R1A475M050BC" 0402L 696.02,1482.79 r270 bottom value=4.7uF
C86 "CGA2B3X7R1H104K050BB" 0402L 655.56,1482.79 r270 bottom value=0.1uF
C87 "C1005X5R1A475M050BC" 0402L 655.56,2081.49 r90 bottom value=4.7uF
C88 "CGA2B3X7R1H104K050BB" 0402L 698.54,2081.49 r90 bottom value=0.1uF
C89 "06035A181JAT2A" 0603L 246.59,1508.11 r0 bottom value=180pF
C90 "06035A100JAT2A" 0603L 207.22,1921.64 r0 bottom value=10pF
C91 "06035A100JAT2A" 0603L 238.72,1730 r180 bottom value=10pF
D1 "SK56A-LTP" SMA 2647,2331.61 r90 bottom value=60V
D2 "BAT42WS-7-F" SOD-323 1950.42,2006.41 r0 bottom value=30V
D3 "SMBJ48A-13-F" SMB 1767.6,2940.2 r0 top value=48V
D4 "LW QH8G-Q2S2-3K5L-1" "LW QH8G_White" 442.28,2986.62 r270 top value=White
D5 "BAT42WS-7-F" SOD-323 1955.33,2094.42 r0 bottom value=30V
D6 "LW QH8G-Q2S2-3K5L-1" "LW QH8G_White" 3079.1,2986.62 r270 top value=White
D7 "150060BS75000" WL-SMCW_Blue 2224.88,285.16 r270 top value=Blue
D8 "1SS315TPH3F" SOD-323 379.35,1454.56 r180 bottom value=5V
D10 "BAT42WS-7-F" SOD-323 1205.82,2932.28 r180 top value=30V
D12 "NSR05F30NXT5G" DSN2_0402 3081.51,755.19 r0 bottom value=30V
D13 "PMEG1030EJ,115" SOD-323F 802.42,2619.74 r0 top value=10V
D20 "SMBJ48A-13-F" SMB 3130.65,1548.31 r90 top value=48V
D22 "SMBJ48A-13-F" SMB 3031.41,954.67 r270 bottom value=48V
D23 "LW QH8G-Q2S2-3K5L-1" "LW QH8G_White" 1312.93,1051.58 r180 top value=White
D26 "LW QH8G-Q2S2-3K5L-1" "LW QH8G_White" 1312.93,1350 r180 top value=White
FID1 "Fiducial" Fiducial10-20 230,769 r90 top
FID2 "Fiducial" Fiducial10-20 2353.52,3002.54 r90 top
FID3 "Fiducial" Fiducial10-20 132,2628 r90 top
H1 "NY PMS 440 0025 PH" "NY PMS 440 0025 PH" 200,200 r0 top
H2 "NY PMS 440 0025 PH" "NY PMS 440 0025 PH" 3312.01,223 r0 top
H3 "NY PMS 440 0025 PH" "NY PMS 440 0025 PH" 200,2900 r0 top
H4 "NY PMS 440 0025 PH" "NY PMS 440 0025 PH" 3312.01,2900 r0 top
H5 "1902C" Keystone_1902C 200,200 r180 bottom
H6 "1902C" Keystone_1902C 3312.01,223 r180 bottom
H7 "1902C" Keystone_1902C 200,2900 r180 bottom
H8 "1902C" Keystone_1902C 3312.01,2900 r180 bottom
J1 "XT30PW-M" FP-XT30PW-M_CONN_PLUG2-MFG 3322.83,1550 r90 bottom
J2 "TSM-108-01-L-DV" Samtec_TSM-108-01-x-DV 858.44,1000 r180 top
J3 "DX07S024JJ2R1300" JAE_DX07S024JJ2R1300 2717.83,3103 r0 bottom
J4 "DX07S024JJ2R1300" JAE_DX07S024JJ2R1300 1756.05,-0.66 r0 top
J5 "54202-G0810LF" FCI_54202-G0810LF 2699.48,1000 r0 top locked
J6 "DX07S024JJ2R1300" JAE_DX07S024JJ2R1300 806.87,3102.75 r0 bottom
J7 "XT30PW-F" FP-XT30PW-F_CONN_SOCKET_DC2-MFG 3536.4,950 r90 bottom
J8 "XT30PW-F" FP-XT30PW-F_CONN_SOCKET_DC2-MFG 1757.43,3139.42 r180 bottom
J9 "TSW-104-07-G-D" TSW-104-07-G-D 3327.95,2201.57 r90 top
J10 "61300411121" WURTH_61300411121 200,2252.22 r90 bottom
J11 "PEC02SAAN" CONN_PEC02SAAN 1651.69,1662.05 r90 top
J12 "PEC02SAAN" CONN_PEC02SAAN 1785.2,1660.94 r90 top
J13 "PEC02SAAN" CONN_PEC02SAAN 2983.13,388.99 r0 top
J14 "PEC02SAAN" CONN_PEC02SAAN 1347.65,712.15 r90 top
J15 "PEC02SAAN" CONN_PEC02SAAN 1905.98,1308.98 r180 top
L2 "742792021" 0805L 2630.51,2734.93 r270 top value="22 ohm"
L3 "XAL6060-472MEB" XAL6060 2269.64,1896.07 r180 bottom value=4.7uH
L4 "742792021" 0805L 1998.21,190.72 r270 bottom value="22 ohm"
L5 "742792021" 0805L 1064.09,2932.28 r0 top value="22 ohm"
LBL1 "THT-14-423-10" Label_650x200 820.66,1822.06 r0 top
Logo1 "CE Mark" CE_Mark_5mm 204.58,1091 r0 top
Logo2 "Texas Instruments" TI_Symbol_Overlay_Small 1611.29,785 r0 top
Logo3 "FCC disclaimer" FCC_disclaimer_stacked -707.69,1383.19 r90 top
Logo4 "WEEE logo" WEEE_Minimum 204.58,1432.05 r0 top
P1 "FX8-120P-SV1(91)" Hirose_FX8-120P-SV1 1756.05,2350 r90 top locked
Q3 "SQJB80EP-T1_GE3" FP-SQJB80EP-T1_GE3_SO-8L-DUAL-MFG 2805.69,1044.46 r180 bottom
Q6 "CSD17484F4T" YJJ0003A 1752.26,649.59 r180 bottom value=30V
Q7 "CSD17484F4T" YJJ0003A 1737.58,704.72 r90 bottom value=30V
Q8 "CSD17581Q3A" DNH0008A 1941.99,404.94 r0 top value=30V
Q15 "CSD15380F3" YJM0003A#1 1184.19,1000 r0 top value=20V
Q18 "CSD15380F3" YJM0003A#1 1184.19,1294.11 r0 top value=20V
QN1 "CSD15380F3" YJM0003A#2 1473.68,477.15 r270 bottom value=20V
QN2 "CSD15380F3" YJM0003A#2 1520.32,477.15 r270 bottom value=20V
QP1 "CSD25480F3" YJM0003A#2 1473.68,274.89 r90 bottom value=-20V
QP2 "CSD25480F3" YJM0003A#2 1520.32,274.88 r90 bottom value=-20V
R1 "CRCW0402100KFKED" 0402L 3260.12,648.75 r0 top value=100k
R2 "ERJ-2RKF1003X" 0402L 1936.3,1364.06 r180 bottom value=100k
R3 "CRCW040210K0JNED" 0402L 1684.43,1832.46 r90 bottom value=10k
R4 "ERJ-H3G0R00V" FP-ERJ-H3G0R00V_0603-MFG 1927.44,1484.79 r0 bottom value=0
R5 "ERJ-H3G0R00V" FP-ERJ-H3G0R00V_0603-MFG 1927.44,1421.47 r0 bottom value=0
R6 "RC0603FR-07100KL" 0603L 2156.09,529.5 r180 top value=100k
R7 "RC0603FR-07100KL" 0603L 2156.09,589.75 r180 top value=100k
R8 "RC0603FR-07100KL" 0603L 2266.48,529.85 r180 top value=100k
R9 "RC0603FR-07100KL" 0603L 2266.48,590.09 r180 top value=100k
R10 "RC0201FS-7D10KL" 0201L 2892.26,566.41 r90 bottom value=10.0k
R11 "CRCW0201200KFKED" 0201_033L 2948.13,2588.06 r0 bottom value=200k
R12 "CRCW0201200KFKED" 0201_033L 2948.13,2616.37 r0 bottom value=200k
R13 "RC0201FR-0751KL" 0201L 2890.61,2587.57 r0 top value=51.0k
R14 "RC0201FR-0751KL" 0201L 2890.61,2616.26 r0 top value=51.0k
R15 "CRCW040210K0JNED" 0402L 3027.59,2915.54 r90 top value=10k
R16 "CRCW02012K20FKED" 0201L 2986.86,2536.78 r270 bottom value=2.20k
R17 "CRCW02012K20FKED" 0201L 2958.54,2536.78 r270 bottom value=2.20k
R18 "CRCW0402100KFKED" 0402L 2595.02,2088.33 r180 top value=100k
R19 "CRCW020110K0FKED" 0201L 640.79,683 r0 bottom value=10.0k
R20 "CRCW0402412KFKED" 0402 2679.84,2016.87 r0 top value=412k
R21 "CRCW0402100KFKED" 0402L 2420.95,2108.56 r180 bottom value=100k
R22 "CRCW0402100KFKED" 0402L 2679.84,1954.86 r0 top value=100k
R23 "ERJ-2RKF2372X" 0402L 2474.55,2130.21 r270 bottom value=23.7k
R24 "CRCW02010000Z0ED" 0201L 1562.99,350.81 r180 bottom value=0
R25 "CRCW02010000Z0ED" 0201L 1429.18,401.37 r0 bottom value=0
R26 "CRCW02010000Z0ED" 0201L 1562.99,401.37 r0 bottom value=0
R27 "CRCW02010000Z0ED" 0201L 1688.72,560.97 r180 top value=0
R28 "CRCW02010000Z0ED" 0201L 1688.72,595.5 r0 top value=0
R29 "CRCW020110K0FKED" 0201L 606.37,543.81 r180 bottom value=10.0k
R30 "CRCW02010000Z0ED" 0201L 1567.99,510.34 r270 bottom value=0
R31 "CRCW04020000Z0ED" 0402 2142.5,793.16 r90 top value=0
R32 "CRCW040210K0FKED" 0402L 2157.62,297.26 r90 top value=10.0k
R34 "RC0201FR-07100KL" 0201L 1690.32,649.59 r180 bottom value=100k
R35 "RC0201FR-07100KL" 0201L 1690.32,717.51 r180 bottom value=100k
R36 "CRCW02012K20FKED" 0201L 1999.46,733.88 r180 top value=2.20k
R37 "CRCW02012K20FKED" 0201L 1999.46,705.85 r180 top value=2.20k
R38 "CRCW020110K0FKED" 0201L 1999.46,761.98 r180 top value=10.0k
R42 "CRCW02012K20FKED" 0201L 1812.18,795.23 r270 top value=2.20k
R43 "CRCW02012K20FKED" 0201L 1840.71,795.23 r270 top value=2.20k
R44 "CRCW020110K0FKED" 0201L 1780.17,795.23 r270 top value=10.0k
R45 "CRCW02010000Z0ED" 0201L 1831.53,369.18 r270 bottom value=0
R46 "CRCW02010000Z0ED" 0201L 1799.79,369.18 r270 bottom value=0
R47 "RC1005F104CS" 0402L 1495.22,225.3 r180 bottom value=100k
R48 "ERJ-2RKF1004X" 0402L 1473.68,331.13 r270 bottom value=1.00Meg
R49 "ERJ-2RKF1004X" 0402L 1520.32,331.12 r270 bottom value=1.00Meg
R50 "ERJ-2RKF1004X" 0402L 1473.68,420.9 r270 bottom value=1.00Meg
R51 "ERJ-2RKF1004X" 0402L 1520.32,420.9 r270 bottom value=1.00Meg
R52 "RC1005F104CS" 0402L 1423.49,480.09 r90 bottom value=100k
R53 "RMCF0402FT1K50" 0402L 610.02,2609.52 r180 bottom value=1.50k
R54 "RC0201FR-075K1L" 0201L 1018.82,2931.17 r270 bottom value=5.10k
R55 "RC0201FR-075K1L" 0201L 669.86,2751.22 r180 bottom value=5.10k
R56 "CRCW040210K0JNED" 0402L 442.28,2878.04 r90 top value=10k
R58 "CRCW0402100KFKED" 0402L 1856.12,1710.94 r90 bottom value=100k
R59 "CRCW020110K0FKED" 0201L 1785.2,1531.9 r270 bottom value=10.0k
R60 "CRCW040210K0JNED" 0402L 393.84,2514.27 r270 bottom value=10k
R63 "RC0402FR-07115KL" 0402L 2027.98,1364.06 r180 bottom value=115k
R65 "CRCW040290K9FKED" 0402L 2385.88,750 r0 bottom value=90.9k
R66 "CRCW040290K9FKED" 0402L 3265.14,1857.16 r180 bottom value=90.9k
R67 "CRCW040210K0JNED" 0402L 346.69,2514.24 r90 bottom value=10k
R69 "CRCW040210K0FKEDC" FP-CRCW040210K0FKEDC_0402-MFG 2286.29,750 r0 bottom value=10k
R70 "CRCW040210K0FKEDC" FP-CRCW040210K0FKEDC_0402-MFG 3363.42,1857.16 r180 bottom value=10k
R71 "CRCW040290K9FKED" 0402L 2688.88,208.47 r180 top value=90.9k
R72 "CRCW040290K9FKED" 0402L 3146.67,1289.32 r270 bottom value=90.9k
R73 "CRCW040210K0FKEDC" FP-CRCW040210K0FKEDC_0402-MFG 2688.88,162 r0 top value=10k
R74 "CRCW040210K0FKEDC" FP-CRCW040210K0FKEDC_0402-MFG 3244.77,1309 r180 bottom value=10k
R77 "CRCW02010000Z0ED" 0201L 1458.07,174.21 r0 top value=0
R78 "CRCW02010000Z0ED" 0201L 1456.74,145.39 r0 top value=0
R79 "CRCW0402100KFKED" 0402L 2263.49,1578.76 r0 bottom value=100k
R80 "CRCW0402100KFKED" 0402L 2182.31,1578.76 r0 bottom value=100k
R81 "RC0201FR-07750RL" 0201L 2388.69,1669.17 r270 bottom value=750
R89 "CRCW02010000Z0ED" 0201L 1153.68,310.49 r270 top value=0
R90 "CRCW02010000Z0ED" 0201L 1125.68,310.49 r270 top value=0
R91 "RC0201FS-7D100KL" 0201L 1346.76,596.42 r270 bottom value=100k
R93 "CRCW040210K0JNED" 0402L 840.51,2694.75 r0 bottom value=10k
R94 "CRCW0402100KFKED" 0402L 3340.54,471.34 r0 bottom value=100k
R95 "CRCW0402100KFKED" 0402L 3254.78,471.34 r0 bottom value=100k
R96 "CRCW040210K0FKED" 0402L 78.13,2399.68 r180 bottom value=10.0k
R97 "CRCW040210K0FKED" 0402L 80,2301.62 r180 bottom value=10.0k
R98 "CRCW040210K0FKED" 0402L 254.46,1454.56 r0 bottom value=10.0k
R137 "CRCW02010000Z0ED" 0201L 3161.21,2304.45 r0 bottom value=0
R139 "CRCW02010000Z0ED" 0201L 3161.21,2352.25 r0 bottom value=0
R149 "CRCW040210K0JNED" 0402L 1262.93,1000 r0 top value=10k
R152 "CRCW040210K0JNED" 0402L 1255.44,1294.11 r0 top value=10k
S2 "B3U-1000P" SW_B3U-1000P 207.22,1603.91 r0 bottom
SH-J11 "SNT-100-BK-G" SNT-100-BK-G 1648.24,1658.56 r90 top value=1x2
SH-J12 "SNT-100-BK-G" SNT-100-BK-G 2985,388 r0 top value=1x2
SH-J13 "SNT-100-BK-G" SNT-100-BK-G 1346.76,715.65 r90 top value=1x2
SH-J14 "SNT-100-BK-G" SNT-100-BK-G 1781.75,1664.44 r90 top value=1x2
SH-J15 "SNT-100-BK-G" SNT-100-BK-G 1902.48,1318.93 r0 top value=1x2
TP1 "5003" Keystone5003 2224.88,147.97 r90 top
TP2 "5117" Keystone5117 2565.47,162 r90 top
TP3 "5002" Keystone5002 1278.9,147.97 r0 top
TP4 "5000" Keystone5000 3210.87,1803.16 r0 top
TP5 "5002" Keystone5002 1001,147.97 r90 top
TP7 "5015" Testpoint_Keystone_Miniature 368.34,2592.04 r0 top
TP10 "5015" Testpoint_Keystone_Miniature 199.58,509.35 r0 top
TP11 "5003" Keystone5003 3188.95,1178.93 r90 top
TP13 "5015" Testpoint_Keystone_Miniature 2923.85,184.43 r0 top
TP14 "5015" Testpoint_Keystone_Miniature 3307.48,2577.36 r180 top
U1 "TLV75733PDRVR" DRV0006A#1 1771.37,1812.01 r90 bottom
U2 "TPS26750RSMR" RSM0032B-MFG 1878.59,649.59 r180 top
U3 "TLV75733PDRVR" DRV0006A#1 1803.14,2149.77 r270 bottom
U4 "TPS259814ARPWR" RPW0010A-MFG 2298.02,1665.03 r0 bottom
U6 "LM2765M6X/NOPB" DBV0006A_N 3074.96,665.12 r180 bottom
U7 "TPS25750DRJK" RJK0038B-C01-MFG 2760.11,2585.23 r180 bottom
U8 "TVS2200DRVR" DRV0006A#2 2721.65,2996.38 r270 top
U9 "LM76005RNPR" RNP0030A 2542.86,1957.87 r0 bottom
U10 "LTC7004IMSE#TRPBF" FP-LTC7004IMSE_TRPBF_MSOP10-MFG 2851.2,802.99 r90 bottom
U12 "TPD4S480RUKR" RUK0020B-MFG 1741.78,454.42 r90 top
U13 "CAT24C512WI-GT3" FP-CAT24C512WI-GT3_SOIC8-IPC_C 1539.41,694.86 r90 bottom
U14 "TUSB2036VFR" VF0032A_L 806.36,2445.94 r270 bottom
U15 "TPD2EUSB30DRTR" DRT0003A 713.17,2673.59 r270 bottom
U17 "TVS0500DRVR" DRV0006A#2 808.77,2996.38 r270 top
U18 "TPD2EUSB30DRTR" DRT0003A 838.03,2205.83 r270 bottom
U19 "TPD2EUSB30DRTR" DRT0003A 800.65,2352.37 r180 top
U20 "TPS7A1650DRBR" DRB0008B 3261.67,593.38 r90 bottom
U22 "TM4C123GH6PMTR" PM0064A_L 665.4,1791.18 r180 bottom
Y1 "ECS-2520MV-480-BN-TR" FP-ECS-2520MV-480-BN-TR_SMT_OSC_2MM5_2MM0-MFG 537.33,2521.31 r0 bottom
Y2 "NX3225GA-16.000M-STD-CRG-1" NDK_NX3225GA 222.97,1824.19 r270 bottom
ZZ1 "This Assembly Note is for PCB labels only" AssemblyNoteLabel 4436.3,667.94 r0 top
ZZ2 "These assemblies are ESD sensitive, ESD precautions shall be observed." AssemblyNote 4435.05,755.54 r0 top
ZZ3 "These assemblies must be clean and free from flux and all contaminants. Use of no clean flux is not acceptable." AssemblyNote 4444.89,834.28 r0 top
ZZ4 "These assemblies must comply with workmanship standards IPC-A-610 Class 2, unless otherwise specified." AssemblyNote 4435.05,922.86 r0 top
ZZ5 "Attach shunts to match jumper instances.  J 11, J12, J13, J14, J15" AssemblyNote 4436.3,590.27 r0 top

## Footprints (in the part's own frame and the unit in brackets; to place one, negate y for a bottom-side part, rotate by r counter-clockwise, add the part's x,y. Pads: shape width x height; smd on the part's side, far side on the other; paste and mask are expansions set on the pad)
0201_033 [mm] "SMD, 2-Leads, Height 0.33mm"
  rect 0.46x0.42 smd mask+0.048: 1(-0.33,0) 2(0.33,0)
  body extent -0.31,-0.16 0.31,0.16, height 0.33
0201_033L [mm] "0201"
  rect 0.36x0.32 smd mask+0.048: 1(-0.28,0) 2(0.28,0)
  body extent -0.31,-0.16 0.31,0.16, height 0.33
0201L [mm] "Data from Kemet datasheet CC101_COM dated 7/28/11"
  rect 0.36x0.32 smd mask+0.048: 1(-0.28,0) 2(0.28,0)
  body extent -0.31,-0.16 0.31,0.16, height 0.26
0402 [mm] "0402 from SM-752 data"
  rect 0.8x0.6 smd: 1(-0.6,0) 2(0.6,0)
  silkscreen extent -1.22,-0.52 1.22,0.52, body extent -0.55,-0.3 0.55,0.3, height 0.6
0402_065L [mm] "0402"
  rect 0.6x0.5 smd: 1(-0.5,0) 2(0.5,0)
  body extent -0.55,-0.3 0.55,0.3, height 0.65
0402_070 [mil] "SMD, 2-Leads, Body 1.2x0.7mm, Height 0.7mm"
  rect 15x24 smd: 1(-20,0) 2(20,0)
  body extent -24,-14 24,14, height 28
0402_080S [mil] "Based on C0402S footprint from PADS legacy"
  rect 15x24 smd: 1(-20,0) 2(20,0)
  body extent -26,-16 26,16, height 31
0402L [mm] "0402 from SM-752 data"
  rect 0.6x0.5 smd: 1(-0.5,0) 2(0.5,0)
  body extent -0.55,-0.3 0.55,0.3, height 0.6
0603L [mm] "0603 from SM-752 data"
  rect 0.8x0.85 smd: 1(-0.7,0) 2(0.7,0)
  silkscreen extent -0.07,-0.32 0.07,0.33, body extent -0.87,-0.47 0.87,0.47, height 1
0805L [mm] "0805 from SM-752 data"
  rect 1.1x1.4 smd: 1(-0.75,0) 2(0.75,0)
  body extent -1.1,-0.72 1.1,0.72, height 1.45
1206_180 [mm] "1206_180"
  rect 1.1x1.6 smd: 1(-1.7,0) 2(1.7,0)
  silkscreen extent -0.9,-1 0.9,1, body extent -1.75,-0.95 1.75,0.95, height 1.8
1210L [mm] "1210 from SM-752 data"
  rect 1.1x2.6 smd: 1(-1.35,0) 2(1.35,0)
  silkscreen extent -0.4,-1.2 0.4,1.2, body extent -1.7,-1.35 1.7,1.35, height 1.35
7343-43 [mm] "Medium density IPC based on Kemet T495 series"
  rect 2.55x2.45 smd: 1(-3.025,0) 2(3.025,0)
  silkscreen extent -4.56,-2.3 3.8,2.3, body extent -3.8,-2.3 3.8,2.3, height 4.3
AssemblyNote [mil] "Assembly Note"
AssemblyNoteLabel [mil] "Assembly Note for PCB Labels"
CE_Mark_5mm [mil] "Minimum text height for CE Mark"
  silkscreen extent -138,-98 138,98
CONN_PEC02SAAN [mm] "SULLINS"
  rrect7% 1.5x1.5 hole 1.016: 1(-1.27,0)
  round 1.5 hole 1.016: 2(1.27,0)
  silkscreen extent -2.54,-1.52 2.54,1.27, body extent -2.54,-1.27 2.54,1.27, height 8.38
DBV0006A_N [mm] "SOT23, 6-Leads, Body 2.9x1.6mm, Pitch 0.95mm, Lead Span 2.8mm, IPC Medium Density"
  rrect17% 1x0.6 smd: 1(-1.375,0.95) 2(-1.375,0) 3(-1.375,-0.95) 4(1.375,-0.95) 5(1.375,0) 6(1.375,0.95)
  silkscreen extent -1.68,-1.55 0.5,1.55, body extent -1.42,-1.46 1.42,1.46, height 1.12
DNH0008A [mm] "VSONP-8"
  rrect50% 0.7x0.4 smd paste-0.05 mask-0.05: 1(-1.55,0.975) 2(-1.55,0.325) 3(-1.55,-0.325) 4(-1.55,-0.975) 5(1.55,-0.975) 6(1.55,-0.325) 7(1.55,0.325) 8(1.55,0.975)
  rrect4% 2.51x2.55 smd paste-1.5 mask-1.5: 9(0.645,0)
  rrect14% 0.705x1.125 on Top Paste: 9A(-0.207,0.662) 9B(0.697,0.662) 9C(-0.207,-0.662) 9D(0.697,-0.662)
  silkscreen extent -1.62,-1.7 1.62,1.7, body extent -1.65,-1.66 1.65,1.66, height 0.91
DRB0008B [mm] "SON, 8-Leads, Body 3x3mm, Pitch 0.65mm, Thermal Pad 2.4x1.65mm, TI Recommended"
  rrect33% 0.6x0.3 smd: 1(-1.4,0.975) 2(-1.4,0.325) 3(-1.4,-0.325) 4(-1.4,-0.975) 5(1.4,-0.975) 6(1.4,-0.325) 7(1.4,0.325) 8(1.4,0.975)
  rrect9% 1.47x1.06 on Bottom Paste: 9(0,-0.63) 9(0,0.63)
  rrect6% 1.65x2.4 smd paste-1.2: 9(0,0)
  silkscreen extent -1.73,-1.72 1.73,1.73, body extent -1.5,-1.5 1.5,1.5, height 0.96
DRT0003A [mm] "SOTFL, 3-Leads, Body 1x1mm (inc leads), Pitch 0.35mm"
  rect 0.45x0.3 smd: 1(-0.575,0.35) 2(-0.575,-0.35) 3(0.575,0)
  silkscreen extent -0.03,-0.6 0.5,0.6, body extent -0.5,-0.5 0.5,0.5, height 0.5
DRV0006A#1 [mm] "SON, 6-Leads, Body 2x2mm, Pitch 0.65mm, Thermal Pad 1.6x1mm, TI Recommended"
  rrect33% 0.45x0.3 smd: 1(-0.975,0.65) 2(-0.975,0) 3(-0.975,-0.65) 4(0.975,-0.65) 5(0.975,0) 6(0.975,0.65)
  rrect14% 1x0.7 on Bottom Paste: 7(0,-0.45) 7(0,0.45)
  rrect10% 1x1.6 smd paste-0.5: 7(0,0)
  silkscreen extent -1.05,-1.2 1.05,1.2, body extent -1.05,-1.05 1.05,1.05, height 0.81
DRV0006A#2 [mm] "SON, 6-Leads, Body 2x2mm, Pitch 0.65mm, Thermal Pad 1.6x1mm, TI Recommended"
  rrect33% 0.45x0.3 smd: 1(-0.975,0.65) 2(-0.975,0) 3(-0.975,-0.65) 4(0.975,-0.65) 5(0.975,0) 6(0.975,0.65)
  rrect14% 1x0.7 on Top Paste: 7(0,0.45) 7(0,-0.45)
  rrect10% 1x1.6 smd paste-0.5: 7(0,0)
  silkscreen extent -1.05,-1.2 1.05,1.2, body extent -1.05,-1.05 1.05,1.05, height 0.81
DSN2_0402 [mm] "ON SEMICONDUCTOR"
  rect 0.47x0.6 smd: 1(-0.367,0)
  rect 0.6x0.6 smd: 2(0.307,0)
  silkscreen extent -0.89,-0.22 -0.89,0.25, body extent -0.5,-0.3 0.5,0.3, height 0.32
FCC_disclaimer_stacked [mil]
FCI_54202-G0810LF [mm] "Header, 2.54mm, 10x2, SMT"
  rrect8% 3.18x1.27 smd: A01(-2.73,11.43) A02(-2.73,8.89) A03(-2.73,6.35) A04(-2.73,3.81) A05(-2.73,1.27) A06(-2.73,-1.27) A07(-2.73,-3.81) A08(-2.73,-6.35) A09(-2.73,-8.89) A10(-2.73,-11.43) B01(2.73,11.43) B02(2.73,8.89) B03(2.73,6.35) B04(2.73,3.81) B05(2.73,1.27) B06(2.73,-1.27) B07(2.73,-3.81) B08(2.73,-6.35) B09(2.73,-8.89) B10(2.73,-11.43)
  silkscreen extent -2.06,-12.5 2.06,12.9, body extent -3.65,-12.5 3.64,12.5, height 9.66
Fiducial10-20 [mm]
  round 1 smd mask+0.5: 1(0,0)
  Top Layer keep-out circle w1.178: c0,0 r0.5
FP-C2012X5R2A475K125AC_0805-MFG [mm]
  rrect13% 0.8x1.05 smd paste+0 mask+0: 1(-0.925,0) 2(0.925,0)
  silkscreen extent -0.15,-0.75 0.15,0.75, body extent -1,-0.63 1,0.63, height 1.5
FP-CAT24C512WI-GT3_SOIC8-IPC_C [mil]
  rrect18% 73.78x21.45 smd paste+0 mask+0: 1(-91.18,75)
  rrect100% 73.78x21.45 smd paste+0 mask+0: 2(-91.18,25) 3(-91.18,-25) 4(-91.18,-75) 5(91.18,-75) 6(91.18,-25) 7(91.18,25) 8(91.18,75)
  silkscreen extent -167,-96 35,96, body extent -118,-96 118,96, height 69
FP-CRCW040210K0FKEDC_0402-MFG [mm]
  rrect25% 0.4x0.6 smd paste+0 mask+0: 1(-0.45,0) 2(0.45,0)
  silkscreen extent -0.55,-0.67 0.55,0.68, body extent -0.5,-0.25 0.5,0.25, height 0.35
FP-ECS-2520MV-480-BN-TR_SMT_OSC_2MM5_2MM0-MFG [mm]
  rrect13% 0.9x0.8 smd paste+0 mask+0: 1(-0.925,-0.725) 2(0.925,-0.725) 3(0.925,0.725) 4(-0.925,0.725)
  silkscreen extent -1.05,-1.8 0.1,1.05, body extent -1.25,-1 1.25,1, height 0.9
FP-ERJ-H3G0R00V_0603-MFG [mm]
  rrect15% 0.65x0.9 smd paste+0 mask+0: 1(-0.725,0) 2(0.725,0)
  silkscreen extent 0,-0.47 0,0.48, body extent -0.8,-0.4 0.8,0.4, height 0.55
FP-LTC7004IMSE_TRPBF_MSOP10-MFG [mm]
  rrect33% 0.889x0.305 smd paste+0 mask+0: 1(-2.106,1) 2(-2.106,0.5) 3(-2.106,0) 4(-2.106,-0.5) 5(-2.106,-1) 6(2.105,-1) 7(2.105,-0.5) 8(2.105,0) 9(2.105,0.5) 10(2.105,1)
  rrect6% 1.68x1.88 smd paste+0 mask+0: 11(0,0)
  silkscreen extent -3.32,-1.55 1.55,1.55, body extent -2.45,-1.5 2.45,1.5, height 1.1
FP-SQJB80EP-T1_GE3_SO-8L-DUAL-MFG [mm]
  rrect24% 0.41x0.72 smd paste+0 mask+0: 1(-1.905,-2.715) 2(-0.635,-2.715) 3(0.635,-2.715) 4(1.905,-2.715)
  round 1.563 smd paste+0 mask+0: 5(1.118,-0.047) 6(-1.118,-0.047)
  Top Layer region: 1.98,-0.915 1.98,-0.255 2.565,-0.255 2.565,0.255 1.98,0.255 1.98,2.665 2.45,2.665 2.45,3.075 0.25,3.075 0.25,-0.915
  Top Layer region: -1.98,-0.915 -1.98,-0.255 -2.565,-0.255 -2.565,0.255 -1.98,0.255 -1.98,2.665 -2.45,2.665 -2.45,3.075 -0.25,3.075 -0.25,-0.915
  silkscreen extent -2.8,-2.84 2.5,2.29, body extent -2.57,-3.08 2.57,3.15, height 1.27
FP-XT30PW-F_CONN_SOCKET_DC2-MFG [mm]
  rrect4% 2.6x2.6 hole 1.7 paste-2539.97 mask+0: 1(-2.5,-8.825)
  round 2.6 hole 1.7 paste-2539.97 mask+0: 2(2.5,-8.825)
  round 1.55 hole 1 paste-2539.97 mask+0: 3(-5.5,-3.825) 4(5.5,-3.825)
  silkscreen extent -6.65,-8.95 6.65,5.08, body extent -6.65,-9.83 6.65,5.07, height 5
FP-XT30PW-M_CONN_PLUG2-MFG [mm]
  rrect4% 2.6x2.6 hole 1.7 paste-2539.97 mask+0: 1(2.5,-8.6)
  round 2.6 hole 1.7 paste-2539.97 mask+0: 2(-2.5,-8.6)
  round 1.55 hole 1 paste-2539.97 mask+0: 3(-5.5,1.4) 4(5.5,1.4)
  silkscreen extent -6.65,-8.72 6.65,4.5, body extent -6.65,-9.45 6.65,4.5, height 5.1
Hirose_FX8-120P-SV1 [mm] "Header(shrouded), 0.6mm, 60x2, SMD"
  rrect29% 1.5x0.35 smd: 1(-2.7,17.7) 2(2.7,17.7) 3(-2.7,17.1) 4(2.7,17.1) 5(-2.7,16.5) 6(2.7,16.5) 7(-2.7,15.9) 8(2.7,15.9) 9(-2.7,15.3) 10(2.7,15.3) 11(-2.7,14.7) 12(2.7,14.7) 13(-2.7,14.1) 14(2.7,14.1) 15(-2.7,13.5) 16(2.7,13.5) 17(-2.7,12.9) 18(2.7,12.9) 19(-2.7,12.3) 20(2.7,12.3) 21(-2.7,11.7) 22(2.7,11.7) 23(-2.7,11.1) 24(2.7,11.1) 25(-2.7,10.5) 26(2.7,10.5) 27(-2.7,9.9) 28(2.7,9.9) 29(-2.7,9.3) 30(2.7,9.3) 31(-2.7,8.7) 32(2.7,8.7) 33(-2.7,8.1) 34(2.7,8.1) 35(-2.7,7.5) 36(2.7,7.5) 37(-2.7,6.9) 38(2.7,6.9) 39(-2.7,6.3) 40(2.7,6.3) 41(-2.7,5.7) 42(2.7,5.7) 43(-2.7,5.1) 44(2.7,5.1) 45(-2.7,4.5) 46(2.7,4.5) 47(-2.7,3.9) 48(2.7,3.9) 49(-2.7,3.3) 50(2.7,3.3) 51(-2.7,2.7) 52(2.7,2.7) 53(-2.7,2.1) 54(2.7,2.1) 55(-2.7,1.5) 56(2.7,1.5) 57(-2.7,0.9) 58(2.7,0.9) 59(-2.7,0.3) 60(2.7,0.3) 61(-2.7,-0.3) 62(2.7,-0.3) 63(-2.7,-0.9) 64(2.7,-0.9) 65(-2.7,-1.5) 66(2.7,-1.5) 67(-2.7,-2.1) 68(2.7,-2.1) 69(-2.7,-2.7) 70(2.7,-2.7) 71(-2.7,-3.3) 72(2.7,-3.3) 73(-2.7,-3.9) 74(2.7,-3.9) 75(-2.7,-4.5) 76(2.7,-4.5) 77(-2.7,-5.1) 78(2.7,-5.1) 79(-2.7,-5.7) 80(2.7,-5.7) 81(-2.7,-6.3) 82(2.7,-6.3) 83(-2.7,-6.9) 84(2.7,-6.9) 85(-2.7,-7.5) 86(2.7,-7.5) 87(-2.7,-8.1) 88(2.7,-8.1) 89(-2.7,-8.7) 90(2.7,-8.7) 91(-2.7,-9.3) 92(2.7,-9.3) 93(-2.7,-9.9) 94(2.7,-9.9) 95(-2.7,-10.5) 96(2.7,-10.5) 97(-2.7,-11.1) 98(2.7,-11.1) 99(-2.7,-11.7) 100(2.7,-11.7) 101(-2.7,-12.3) 102(2.7,-12.3) 103(-2.7,-12.9) 104(2.7,-12.9) 105(-2.7,-13.5) 106(2.7,-13.5) 107(-2.7,-14.1) 108(2.7,-14.1) 109(-2.7,-14.7) 110(2.7,-14.7) 111(-2.7,-15.3) 112(2.7,-15.3) 113(-2.7,-15.9) 114(2.7,-15.9) 115(-2.7,-16.5) 116(2.7,-16.5) 117(-2.7,-17.1) 118(2.7,-17.1) 119(-2.7,-17.7) 120(2.7,-17.7)
  round 0 hole 1.1 unplated: ""(-1.5,20.1)
  round 0 hole 0.7 unplated: ""(-1.5,-20.1)
  silkscreen extent -3.1,-21.45 2.7,21.45, body extent -2.7,-21.45 2.7,21.45, height 4
JAE_DX07S024JJ2R1300 [mm] "Receptacle, USB 3.1 Type C, R/A, SMT"
  rrect37% 0.27x0.9 smd: A1(-2.625,7.55) A2(-2.125,7.55) A3(-1.625,7.55) A4(-1.125,7.55) A5(-0.625,7.55) A6(-0.125,7.55) A7(0.375,7.55) A8(0.875,7.55) A9(1.375,7.55) A10(1.875,7.55) A11(2.375,7.55) A12(2.875,7.55)
  round 0.3 hole 0.6 unplated mask+0.102: ALIGN1(-3.6,4.85)
  rrect100% 0.55x0.3 hole 0.5 slot 0.85 at 0 deg unplated mask+0.102: ALIGN2(3.6,4.915)
  rrect37% 0.27x0.8 smd: B1(2.625,5.95) B2(2.125,5.95) B3(1.625,5.95) B4(1.125,5.95) B5(0.625,5.95) B6(0.125,5.95) B7(-0.375,5.95) B8(-0.875,5.95) B9(-1.375,5.95) B10(-1.875,5.95) B11(-2.375,5.95) B12(-2.875,5.95)
  rrect100% 1.2x2.3 hole 0.6 slot 1.9 at 90 deg: S1(-4.32,6.85) S2(4.32,6.85)
  rrect100% 1.45x1.1 hole 0.7 slot 1.25 at 0 deg: S1(-3.995,6.25) S2(3.995,6.25)
  rrect100% 1.3x2.6 hole 0.7 slot 2 at 90 deg: S3(-4.32,1.8) S4(4.32,1.8)
  body extent -4.47,-0.5 4.47,7.67, height 3.14
Keystone5000 [mil] "For Keystone 500x miniature loop terminals"
  round 80 hole 40: 1(0,0)
  silkscreen extent -52,-52 52,52, body extent -49,-49 49,49, height 182
Keystone5002 [mil] "For Keystone 500x miniature loop terminals"
  round 80 hole 40: 1(0,0)
  silkscreen extent -52,-52 52,52, body extent -49,-49 49,49, height 182
Keystone5003 [mil] "For Keystone 500x miniature loop terminals"
  round 80 hole 40: 1(0,0)
  silkscreen extent -52,-52 52,52, body extent -49,-49 49,49, height 182
Keystone5117 [mil] "For Keystone 500x miniature loop terminals"
  round 80 hole 40: 1(0,0)
  silkscreen extent -52,-52 52,52, body extent -49,-49 49,49, height 182
Keystone_1902C [mil] "Hex Standoff, 4-40 threaded, nylon"
  round 1 on Mech4: 0(0,0)
  body extent -145,-126 146,126, height 501
Label_650x200 [mil] "Thermal Transfer Label"
  round 1 on Mech13: 0(0,0)
  silkscreen extent -325,-100 325,100, body extent -325,-100 325,100, height 1
"LW QH8G_White" [mm] "SMD, 2-Leads, Body 1x0.5mm"
  rect 0.6x0.6 smd paste-0.3: 1(-0.55,0) 2(0.55,0)
  silkscreen extent 1.1,-0.4 1.3,0.4, body extent -0.55,-0.3 0.55,0.3, height 0.4
NDK_NX3225GA [mm] "NDK"
  rect 1.2x1.4 smd: 1(-0.8,1.1) 2(-0.8,-1.1) 3(0.8,-1.1) 4(0.8,1.1)
  silkscreen extent -1.9,-0.1 1.4,2, body extent -1.3,-1.65 1.3,1.65, height 0.9
"NY PMS 440 0025 PH" [mm] "4-40 nylon screw and mounting hole"
  round 8 hole 3.2: 1(0,0)
  body extent -3.3,-3.3 3.3,3.3, height 2.69
PM0064A_L [mm] "Thin QFP, 64-Leads, Body 10x10mm, Pitch 0.5mm, IPC High Density"
  oval 1.25x0.25 smd: 1(-5.625,3.75) 2(-5.625,3.25) 3(-5.625,2.75) 4(-5.625,2.25) 5(-5.625,1.75) 6(-5.625,1.25) 7(-5.625,0.75) 8(-5.625,0.25) 9(-5.625,-0.25) 10(-5.625,-0.75) 11(-5.625,-1.25) 12(-5.625,-1.75) 13(-5.625,-2.25) 14(-5.625,-2.75) 15(-5.625,-3.25) 16(-5.625,-3.75) 33(5.625,-3.75) 34(5.625,-3.25) 35(5.625,-2.75) 36(5.625,-2.25) 37(5.625,-1.75) 38(5.625,-1.25) 39(5.625,-0.75) 40(5.625,-0.25) 41(5.625,0.25) 42(5.625,0.75) 43(5.625,1.25) 44(5.625,1.75) 45(5.625,2.25) 46(5.625,2.75) 47(5.625,3.25) 48(5.625,3.75)
  oval 0.25x1.25 smd: 17(-3.75,-5.625) 18(-3.25,-5.625) 19(-2.75,-5.625) 20(-2.25,-5.625) 21(-1.75,-5.625) 22(-1.25,-5.625) 23(-0.75,-5.625) 24(-0.25,-5.625) 25(0.25,-5.625) 26(0.75,-5.625) 27(1.25,-5.625) 28(1.75,-5.625) 29(2.25,-5.625) 30(2.75,-5.625) 31(3.25,-5.625) 32(3.75,-5.625) 49(3.75,5.625) 50(3.25,5.625) 51(2.75,5.625) 52(2.25,5.625) 53(1.75,5.625) 54(1.25,5.625) 55(0.75,5.625) 56(0.25,5.625) 57(-0.25,5.625) 58(-0.75,5.625) 59(-1.25,5.625) 60(-1.75,5.625) 61(-2.25,5.625) 62(-2.75,5.625) 63(-3.25,5.625) 64(-3.75,5.625)
  silkscreen extent -5.65,-4.35 4.35,4.55, body extent -6.01,-6.01 6.01,6.01, height 1.5
RJK0038B-C01-MFG [mm]
  rrect50% 0.6x0.2 smd paste+0 mask-1000: 1(-2.9,1) 2(-2.9,0.6) 3(-2.9,0.2) 4(-2.9,-0.2) 5(-2.9,-0.6) 6(-2.9,-1)
  rrect50% 0.2x0.6 smd paste+0 mask-1000: 7(-2.4,-1.9) 8(-2,-1.9) 9(-1.6,-1.9) 10(-1.2,-1.9) 11(-0.8,-1.9) 12(-0.4,-1.9) 13(0,-1.9) 14(0.4,-1.9) 15(0.8,-1.9) 16(1.2,-1.9) 17(1.6,-1.9) 18(2,-1.9) 19(2.4,-1.9) 26(2.4,1.9) 27(2,1.9) 28(1.6,1.9) 29(1.2,1.9) 30(0.8,1.9) 31(0.4,1.9) 36(-1.6,1.9) 37(-2,1.9) 38(-2.4,1.9)
  rrect50% 0.4x0.2 smd paste-1000 mask-1000: 20(2.8,-1.1) 21(2.8,-0.65) 22(2.8,-0.2) 23(2.8,0.2) 24(2.8,0.65) 25(2.8,1.1)
  rrect50% 0.2x0.4 smd paste-1000 mask-1000: 32(0,1.8) 33(-0.4,1.8) 34(-0.8,1.8) 35(-1.2,1.8)
  rrect4% 2.72x2.65 smd paste-1000 mask-1000: 39(-0.965,0)
  rrect7% 1.53x2.65 smd paste-1000 mask-1000: 40(1.56,0)
  rrect29% 0.7x0.7 smd paste-1000 mask-1000: ""(-1,1.9) ""(-0.2,1.9)
  rrect29% 0.7x1.253 smd paste-1000 mask-1000: ""(2.9,-0.677) ""(2.9,0.676)
  silkscreen extent -3.98,-2.05 3.05,2.05, body extent -3,-2 3,2, height 0.8
RNP0030A [mm] "QFN, 30-Leads, Body 6x4mm, Pitch 0.5mm, Thermal Pad 4.6x2.2mm"
  rrect40% 0.75x0.25 smd: 1(-1.825,2.5) 2(-1.825,2) 3(-1.825,1.5) 4(-1.825,1) 5(-1.825,0.5) 6(-1.825,0) 7(-1.825,-0.5) 8(-1.825,-1) 9(-1.825,-1.5) 10(-1.825,-2) 11(-1.825,-2.5) 16(1.825,-2.5) 17(1.825,-2) 18(1.825,-1.5) 19(1.825,-1) 20(1.825,-0.5) 21(1.825,0) 22(1.825,0.5) 23(1.825,1) 24(1.825,1.5) 25(1.825,2) 26(1.825,2.5)
  rrect40% 0.25x0.6 smd: 12(-0.75,-2.9) 13(-0.25,-2.9) 14(0.25,-2.9) 15(0.75,-2.9) 27(0.75,2.9) 28(0.25,2.9) 29(-0.25,2.9) 30(-0.75,2.9)
  rrect5% 2.2x4.6 smd paste-3: 31(0,0)
  rrect10% 0.98x0.96 on Bottom Paste: 31A(-0.59,-1.74) 31A(-0.59,-0.58) 31A(-0.59,0.58) 31A(-0.59,1.74) 31A(0.59,-1.74) 31A(0.59,-0.58) 31A(0.59,0.58) 31A(0.59,1.74)
  silkscreen extent -2.17,-3.18 2.18,3.17, body extent -2,-3 2,3, height 0.77
RPW0010A-MFG [mm]
  round 0.27 smd paste-1000 mask+0: 1(-0.75,0.7) 10(0.75,0.7)
  rrect40% 0.6x0.25 smd paste+0 mask+0: 2(-0.9,0.225) 3(-0.9,-0.225) 8(0.9,-0.225) 9(0.9,0.225)
  round 0.255 smd paste-1000 mask+0: 4(-0.75,-0.75) 7(0.75,-0.75)
  rrect33% 0.3x2.4 smd paste-1000 mask+0: 5(-0.25,0) 6(0.25,0)
  Top Layer region: -0.85,-0.85 -0.85,-1.15 -0.846,-1.169 -0.835,-1.185 -0.819,-1.196 -0.8,-1.2 -0.8,-1.2 -0.65,-1.2 -0.631,-1.196 -0.615,-1.185 -0.604,-1.169 -0.6,-1.15 -0.6,-1.15 -0.6,-0.6 -0.604,-0.581 -0.615,-0.565 -0.631,-0.554 -0.65,-0.55 -0.65,-0.55 -1.15,-0.55 -1.169,-0.554 -1.185,-0.565 -1.196,-0.581 -1.2,-0.6 -1.2,-0.6 -1.2,-0.8 -1.196,-0.819 -1.185,-0.835 -1.169,-0.846 -1.15,-0.85 -1.15,-0.85
  Top Layer region: 0.85,-0.85 0.85,-1.15 0.846,-1.169 0.835,-1.185 0.819,-1.196 0.8,-1.2 0.8,-1.2 0.65,-1.2 0.631,-1.196 0.615,-1.185 0.604,-1.169 0.6,-1.15 0.6,-1.15 0.6,-0.6 0.604,-0.581 0.615,-0.565 0.631,-0.554 0.65,-0.55 0.65,-0.55 1.15,-0.55 1.169,-0.554 1.185,-0.565 1.196,-0.581 1.2,-0.6 1.2,-0.6 1.2,-0.8 1.196,-0.819 1.185,-0.835 1.169,-0.846 1.15,-0.85 1.15,-0.85
  Top Layer region: 0.85,0.85 0.85,1.15 0.846,1.169 0.835,1.185 0.819,1.196 0.8,1.2 0.8,1.2 0.65,1.2 0.631,1.196 0.615,1.185 0.604,1.169 0.6,1.15 0.6,1.15 0.6,0.6 0.604,0.581 0.615,0.565 0.631,0.554 0.65,0.55 0.65,0.55 1.15,0.55 1.169,0.554 1.185,0.565 1.196,0.581 1.2,0.6 1.2,0.6 1.2,0.8 1.196,0.819 1.185,0.835 1.169,0.846 1.15,0.85 1.15,0.85
  Top Layer region: -0.85,0.85 -0.85,1.15 -0.843,1.175 -0.825,1.193 -0.8,1.2 -0.8,1.2 -0.65,1.2 -0.631,1.196 -0.615,1.185 -0.604,1.169 -0.6,1.15 -0.6,1.15 -0.6,0.6 -0.604,0.581 -0.615,0.565 -0.631,0.554 -0.65,0.55 -0.65,0.55 -1.15,0.55 -1.169,0.554 -1.185,0.565 -1.196,0.581 -1.2,0.6 -1.2,0.6 -1.2,0.8 -1.193,0.825 -1.175,0.843 -1.15,0.85 -1.15,0.85
  silkscreen extent -1.87,-1.58 1.05,1.57, body extent -1,-1 1,1, height 1
RSM0032B-MFG [mm]
  rrect50% 0.55x0.2 smd paste+0 mask+0: 1(-1.925,1.4) 2(-1.925,1) 3(-1.925,0.6) 4(-1.925,0.2) 5(-1.925,-0.2) 6(-1.925,-0.6) 7(-1.925,-1) 8(-1.925,-1.4) 17(1.925,-1.4) 18(1.925,-1) 19(1.925,-0.6) 20(1.925,-0.2) 21(1.925,0.2) 22(1.925,0.6) 23(1.925,1) 24(1.925,1.4)
  rrect50% 0.2x0.55 smd paste+0 mask+0: 9(-1.4,-1.925) 10(-1,-1.925) 11(-0.6,-1.925) 12(-0.2,-1.925) 13(0.2,-1.925) 14(0.6,-1.925) 15(1,-1.925) 16(1.4,-1.925) 25(1.4,1.925) 26(1,1.925) 27(0.6,1.925) 28(0.2,1.925) 29(-0.2,1.925) 30(-0.6,1.925) 31(-1,1.925) 32(-1.4,1.925)
  rrect4% 2.8x2.8 smd paste-1000 mask+0: 33(0,0)
  silkscreen extent -2.88,-2.05 2.05,2.05, body extent -2.3,-2.3 2.3,2.3, height 0.25
RUK0020B-MFG [mm]
  rrect50% 0.6x0.2 smd paste+0 mask+0: 1(-1.4,0.8) 2(-1.4,0.4) 3(-1.4,0) 4(-1.4,-0.4) 5(-1.4,-0.8) 11(1.4,-0.8) 12(1.4,-0.4) 13(1.4,0) 14(1.4,0.4) 15(1.4,0.8)
  rrect50% 0.2x0.6 smd paste+0 mask+0: 6(-0.8,-1.4) 7(-0.4,-1.4) 8(0,-1.4) 9(0.4,-1.4) 10(0.8,-1.4) 16(0.8,1.4) 17(0.4,1.4) 18(0,1.4) 19(-0.4,1.4) 20(-0.8,1.4)
  rrect6% 1.7x1.7 smd paste-1000 mask+0: 21(0,0)
  silkscreen extent -2.4,-1.55 1.55,1.55, body extent -1.8,-1.8 1.8,1.8, height 0.25
Samtec_TSM-108-01-x-DV [mm] "Header, 2.54mm, 8x2, SMT"
  rect 3.68x1.27 smd: 1(-2.475,8.89) 2(2.475,8.89) 3(-2.475,6.35) 4(2.475,6.35) 5(-2.475,3.81) 6(2.475,3.81) 7(-2.475,1.27) 8(2.475,1.27) 9(-2.475,-1.27) 10(2.475,-1.27) 11(-2.475,-3.81) 12(2.475,-3.81) 13(-2.475,-6.35) 14(2.475,-6.35) 15(-2.475,-8.89) 16(2.475,-8.89)
  silkscreen extent -1.65,-10.16 1.65,10.3, body extent -3.85,-10.16 3.85,10.16, height 9.65
SMA [mm] "Molded Diode, 2-Leads, Body 4.3x2.6mm, IPC Medium Density, based on OnSemi component dimensions and land pattern"
  rect 2x2 smd: 1(-2,0) 2(2,0)
  silkscreen extent -3.66,-1.58 2.79,1.57, body extent -2.6,-1.3 2.6,1.3, height 2.42
SMB [mil] "Molded Diode, 2-Leads, Body 5.4x3.6mm, IPC Medium Density, based on OnSemi component dimensions"
  rect 85x107.99 smd: 1(-87.01,0) 2(87.01,0)
  silkscreen extent -155,-82 125,82, body extent -106,-71 106,71, height 91
SNT-100-BK-G [mil] "Samtec STEP model"
  round 1 on Mech3: 0(0,0)
  body extent -100,-50 100,50, height 344
SOD-323 [mm] "NXP recommended land pattern"
  rect 0.6x0.6 smd paste-0.05: 1(-1.1,0) 2(1.1,0)
  silkscreen extent -2.06,-0.86 1.52,0.86, body extent -1.3,-0.67 1.3,0.68, height 1.1
SOD-323F [mm] "NXP recommended land pattern"
  rect 0.6x0.6 smd paste-0.05: 1(-1.1,0) 2(1.1,0)
  silkscreen extent -2.06,-0.86 1.53,0.86, body extent -1.35,-0.67 1.35,0.67, height 0.79
SW_B3U-1000P [mm] "OMRON"
  rect 0.8x1.7 smd: 1(-1.7,0) 2(1.7,0)
  silkscreen extent -1.5,-1.25 1.5,1.25, body extent -1.5,-1.25 1.5,1.25, height 1.75
Testpoint_Keystone_Miniature [mil] "Miniature SMT test point"
  rect 135x70 smd: 1(0,0)
  silkscreen extent -78,-46 78,45, body extent -52,-20 52,20, height 61
TI_Symbol_Overlay_Small [mil]
  silkscreen extent -90,-88 91,88
TSW-104-07-G-D [mm] "Samtec 100mil, 2x4, 230 mil above insulator"
  rrect6% 1.65x1.65 hole 1.016: 1(-3.81,-1.27)
  round 1.65 hole 1.016: 2(-3.81,1.27) 3(-1.27,-1.27) 4(-1.27,1.27) 5(1.27,-1.27) 6(1.27,1.27) 7(3.81,-1.27) 8(3.81,1.27)
  silkscreen extent -6.1,-2.54 5.08,2.54, body extent -5.08,-2.54 5.08,2.54, height 8.38
VF0032A_L [mm] "Thin QFP, 32-Leads, Body 7x7mm, Pitch 0.8mm, IPC High Density"
  oval 1.25x0.5 smd: 1(-4.15,2.8) 2(-4.15,2) 3(-4.15,1.2) 4(-4.15,0.4) 5(-4.15,-0.4) 6(-4.15,-1.2) 7(-4.15,-2) 8(-4.15,-2.8) 17(4.1,-2.8) 18(4.1,-2) 19(4.1,-1.2) 20(4.1,-0.4) 21(4.1,0.4) 22(4.1,1.2) 23(4.1,2) 24(4.1,2.8)
  oval 0.5x1.25 smd: 9(-2.825,-4.125) 10(-2.025,-4.125) 11(-1.225,-4.125) 12(-0.425,-4.125) 13(0.375,-4.125) 14(1.175,-4.125) 15(1.975,-4.125) 16(2.775,-4.125) 25(2.775,4.125) 26(1.975,4.125) 27(1.175,4.125) 28(0.375,4.125) 29(-0.425,4.125) 30(-1.225,4.125) 31(-2.025,4.125) 32(-2.825,4.125)
  silkscreen extent -4.27,-3.05 3.05,3.75, body extent -4.51,-4.51 4.51,4.51, height 1.6
WEEE_Minimum [mil] "WEEElie bin"
  silkscreen extent -95,-172 99,104
WL-SMCW_Blue [mm] "SMD, 2-Leads, Body 1.6x0.8mm"
  rect 0.8x0.8 smd: 1(-0.8,0) 2(0.8,0)
  silkscreen extent -1.9,-0.8 1.2,0.8, body extent -0.85,-0.45 0.85,0.45, height 0.8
